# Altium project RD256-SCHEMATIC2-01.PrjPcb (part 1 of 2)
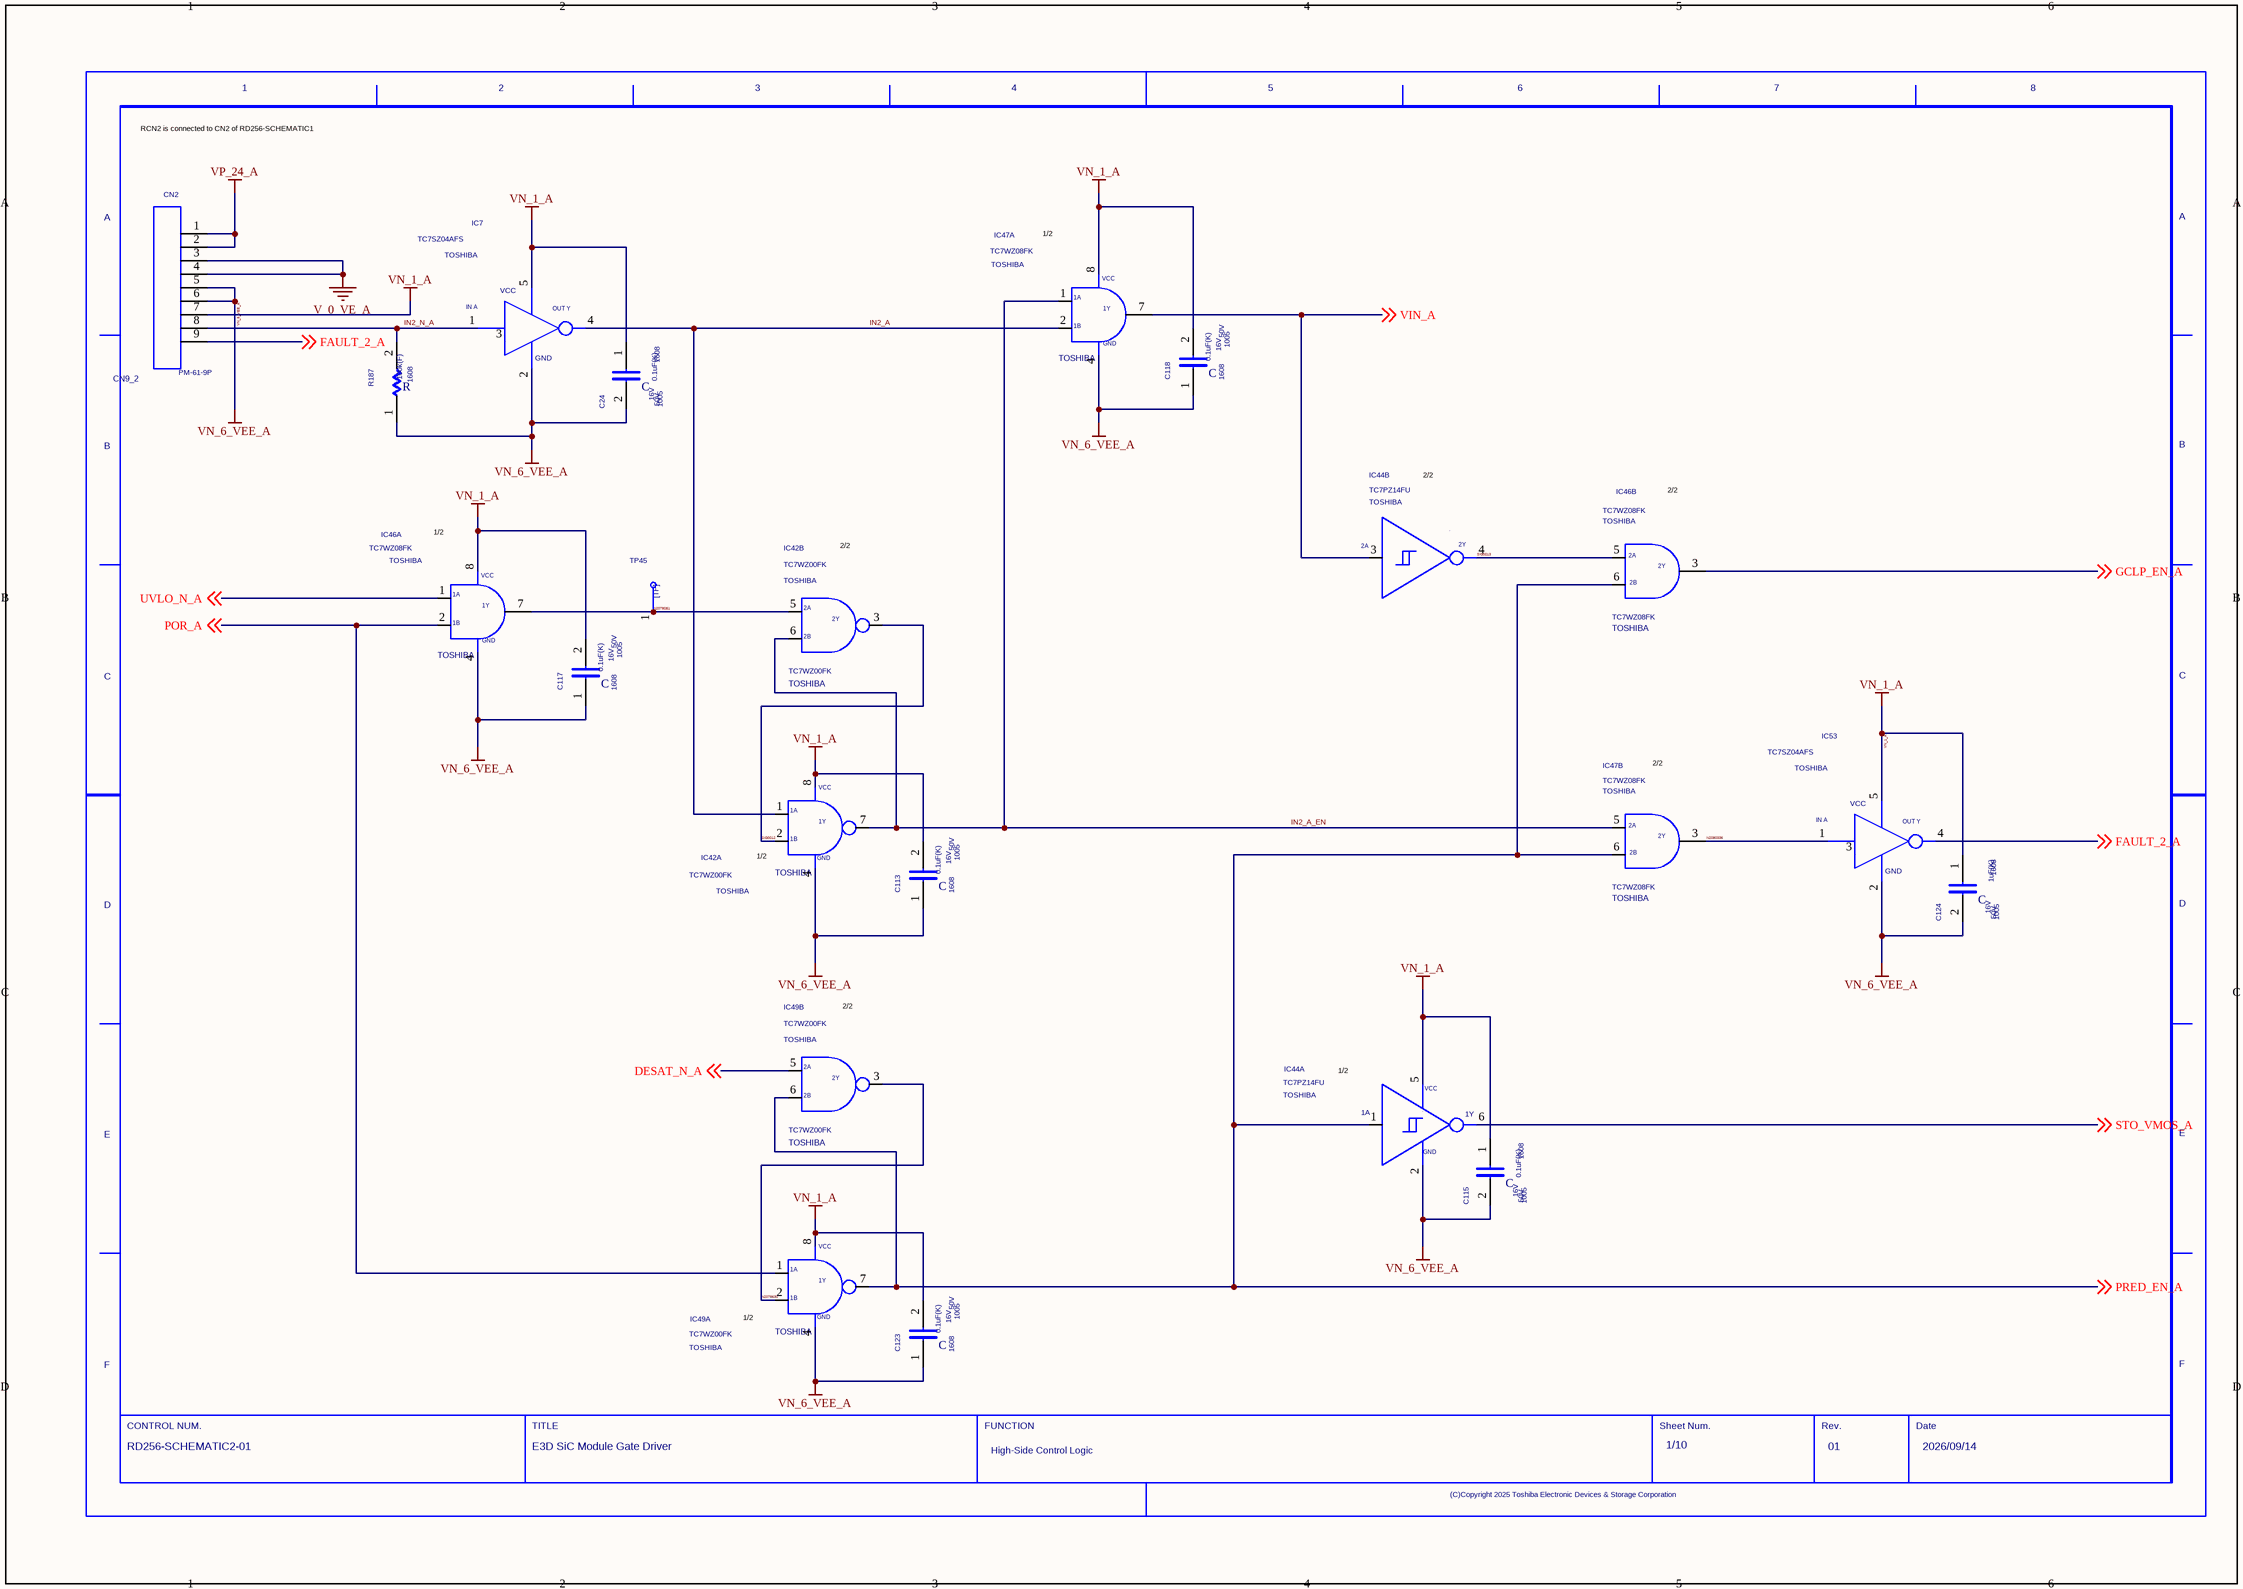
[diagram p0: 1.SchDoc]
10 sheets, 363 parts. Net scope: global (net labels, ports and power ports of the same name join across sheets).
Sheets:
  1.SchDoc
  2.SchDoc
  3.SchDoc
  4.SchDoc
  5.SchDoc
  6.SchDoc
  7.SchDoc
  8.SchDoc
  9.SchDoc
  10.SchDoc

## Sheet 1.SchDoc
size 420 x 297 mm

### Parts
(Parts that share a designator on the sheet are numbered #1, #2 ... from top to bottom, then left to right.)
C24  VOLTAGE: 16V  CODE: 1005  VAL1: 0.1uF(K)  VAL2: 50V  SIZECODESMD: 1608  (hidden comment: C)
C113  VOLTAGE: 16V  CODE: 1005  VAL1: 0.1uF(K)  VAL2: 50V  SIZECODESMD: 1608  (hidden comment: C)
C115  VOLTAGE: 16V  CODE: 1005  VAL1: 0.1uF(K)  VAL2: 50V  SIZECODESMD: 1608  (hidden comment: C)
C117  VOLTAGE: 16V  CODE: 1005  VAL1: 0.1uF(K)  VAL2: 50V  SIZECODESMD: 1608  (hidden comment: C)
C118  VOLTAGE: 16V  CODE: 1005  VAL1: 0.1uF(K)  VAL2: 50V  SIZECODESMD: 1608  (hidden comment: C)
C123  VOLTAGE: 16V  CODE: 1005  VAL1: 0.1uF(K)  VAL2: 50V  SIZECODESMD: 1608  (hidden comment: C)
C124  VOLTAGE: 16V  CODE: 1005  VAL1: 1uF(K)  VAL2: 50V  SIZECODESMD: 1608  (hidden comment: C)
CN2  CN9_2  VAL3: PM-61-9P
IC7  USERCOMPTEXT3: TOSHIBA  (hidden comment: TC7SZ04AFS)
IC42  VENDOR: TOSHIBA  (hidden comment: TC7WZ00FK)  (parts A,B of 2)
IC44  VAL3: TC7PZ14FU  USERCOMPTEXT3: TOSHIBA  (hidden comment: TC7PZ17FU)  (parts A,B of 2)
IC46  VENDOR: TOSHIBA  (hidden comment: TC7WZ08FK)  (parts A,B of 2)
IC47  VENDOR: TOSHIBA  (hidden comment: TC7WZ08FK)  (parts A,B of 2)
IC49  VENDOR: TOSHIBA  (hidden comment: TC7WZ00FK)  (parts A,B of 2)
IC53  USERCOMPTEXT3: TOSHIBA  (hidden comment: TC7SZ04AFS)
R187  VAL1: 100k(F)  SIZECODESMD: 1608  (hidden comment: R)
TP45  TP  (value not drawn)
U?#1  REVISION: 01  SHEETNUMBER: 1/10  FUNCTION: High-Side Control Logic  TITLE: E3D SiC Module Gate Driver  DRAWINGNUMBER: RD256-SCHEMATIC2-01  DATE: 2026/09/14  (hidden comment: WAKU_DEF100)

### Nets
V_0_VE_A: CN2.3 CN2.4
VN_1_A: C24.1 C113.2 C115.1 C117.2 C118.2 C123.2 C124.1 CN2.7 IC7.5 IC42.8 IC44.5 IC46.8 IC47.8 IC49.8 IC53.5
VN_6_VEE_A: C24.2 C113.1 C115.2 C117.1 C118.1 C123.1 C124.2 CN2.5 CN2.6 IC7.2 IC42.4 IC44.2 IC46.4 IC47.4 IC49.4 IC53.2 R187.1
VP_24_A: CN2.1 CN2.2
DESAT_N_A: IC49.5(2A) ; off-sheet DESAT_N_A
FAULT_2_A: CN2.9 IC53.4 ; off-sheet FAULT_2_A
GCLP_EN_A: IC46.3 ; off-sheet GCLP_EN_A
IN2_A: IC7.4 IC42.1 IC47.2
IN2_A_EN: IC42.6(2B) IC42.7 IC47.1 IC47.5
IN2_N_A: CN2.8 IC7.1 R187.2
N2078081: IC42.5(2A) IC46.7 TP45.1
N2078630: IC49.2 IC49.3(2Y)
N2080336: IC47.3 IC53.1
POR_A: IC46.2 IC49.1 ; off-sheet POR_A
PRED_EN_A: IC44.1 IC46.6 IC47.6 IC49.6(2B) IC49.7 ; off-sheet PRED_EN_A
SIG0012: IC42.2 IC42.3(2Y)
SIG0013: IC44.4 IC46.5
STO_VMOS_A: IC44.6 ; off-sheet STO_VMOS_A
UVLO_N_A: IC46.1 ; off-sheet UVLO_N_A
VIN_A: IC44.3 IC47.7 ; off-sheet VIN_A

Not connected (* = marked no-connect by the designer): IC7 3; IC53 3

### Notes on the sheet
- RCN2 is connected to CN2 of RD256-SCHEMATIC1
- (near IC47) 1/2
- (near IC46) 1/2
- 2/2
- (near IC42) 1/2
- (near IC44) 1/2
- (near IC49) 1/2

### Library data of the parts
C24 C113 C115 C117 C118 C123 C124 = C: ORIGINALSYMBOLORIGIN: (0,0); VC2: 0; PSPICETEMPLATE: C^@REFDES %1 %2 ?TOLERANCE¦C^@REFDES¦ @VALUE ?IC/IC=@IC/ TC=@TC1,@TC2 ?TOLERANCE¦\n.model C^@REFDES CAP C=1 DEV=@TOLERANCE% TC1=@TC1 TC2=@TC2 VC1=@VC1 VC2=@VC2¦; SAVECOUNT: 2; UPDATETIME: 08:48:12; UPDATEUSER: HP_Z8_KEYSHOT; INSTANCENAME: INS2265204
CN2 = CN9_1: OriginalSymbolOrigin: (0,0); USER_VALUE: XG4A-1031; PSPICETEMPLATE: X^@REFDES %1 %2 %3 %4 %5 %6 %7 %8 %9 %10 %M1 %M2 @MODEL; SAVECOUNT: 2; UPDATETIME: 08:48:13; UPDATEUSER: HP_Z8_KEYSHOT; INSTANCENAME: INS2253568
IC7 IC53 = TC7SZ04AFS: OriginalSymbolOrigin: (0,-5080); PSPICETEMPLATE: X^@REFDES %INA %GND %NC %OUTY %VCC @MODEL; SAVECOUNT: 6; UPDATETIME: 19:30:29; UPDATEUSER: t5459927; TIME: 11:55:02; INSTANCENAME: INS2254048
IC42 IC49 = TC7WZ00FK_2: PART NUMBER: TC7W00FK; ORIGINALSYMBOLORIGIN: (2540,-2540); DESCRIPTION-A: NAND 2ch Logic; PSPICETEMPLATE: X^@REFDES %1A %1B %2Y %GND %2A %2B %1Y %VCC @MODEL; ・: 7 V; SPLIT_INST: TRUE; ORDER: $pOrder; SWAP_INFO: (S1+S2); SAVECOUNT: 5; UPDATETIME: 16:09:46; UPDATEUSER: sptcae09; TIME: 08:52:39; INSTANCENAME: INS2253652; FUNCN: TC7WZ00FK_1; CaptureCellPackProp: TC7WZ00FK_2A
IC44 = TC7PZ14FU_2: OriginalSymbolOrigin: (5080,15240); SWAP_INFO: (S1+S2); PSPICETEMPLATE: X^@REFDES %1A %GND %2A %2Y %VCC %1Y @MODEL; SPLIT_INST: TRUE; SAVECOUNT: 7; UPDATETIME: 19:09:34; UPDATEUSER: t5459927; TIME: 11:55:01; INSTANCENAME: INS2254016; FUNCN: TC7PZ14FU_1; CaptureCellPackProp: TC7PZ14FU_2A
IC46 IC47 = TC7WZ08FK_1: PART NUMBER: TC7W00FK; ORIGINALSYMBOLORIGIN: (2540,-2540); DESCRIPTION-A: NAND 2ch Logic; PSPICETEMPLATE: X^@REFDES %1A %1B %2Y %GND %2A %2B %1Y %VCC @MODEL; ・: 7 V; SPLIT_INST: TRUE; ORDER: $pOrder; SWAP_INFO: (S1+S2); SAVECOUNT: 5; UPDATETIME: 16:09:46; UPDATEUSER: sptcae09; TIME: 08:52:39; INSTANCENAME: INS2254084; CaptureCellPackProp: TC7WZ08FK_1A
R187 = R: ORIGINALSYMBOLORIGIN: (0,0); PSPICETEMPLATE: R^@REFDES %1 %2 ?TOLERANCE¦R^@REFDES¦ @VALUE TC=@TC1,@TC2 ?TOLERANCE¦\n.model R^@REFDES RES R=1 DEV=@TOLERANCE% TC1=@TC1 TC2=@TC2¦; TC2: 0; VAL2: 100mW; SAVECOUNT: 2; UPDATETIME: 08:48:13; UPDATEUSER: HP_Z8_KEYSHOT; INSTANCENAME: INS2263832
TP45 = TP: ORIGINALSYMBOLORIGIN: (0,0); SAVEAREA0: -242,-92,12810,7836; SAVECOUNT: 2; UPDATETIME: 16:18:11; UPDATEUSER: fukuda-y; TIME: 16:12:21; INSTANCENAME: INS2253720
U?#1 = WAKU_DEF100: OriginalSymbolOrigin: (10160,284480); SAVECOUNT: 4; UPDATETIME: 12:22:00; UPDATEUSER: t5459927; TIME: 14:30:25; SAVEAREA0: -63393,-16950,474261,314592; PLOTTIME: HH:MM; SHTSAVECOUNT: 35

## Sheet 2.SchDoc
size 420 x 297 mm
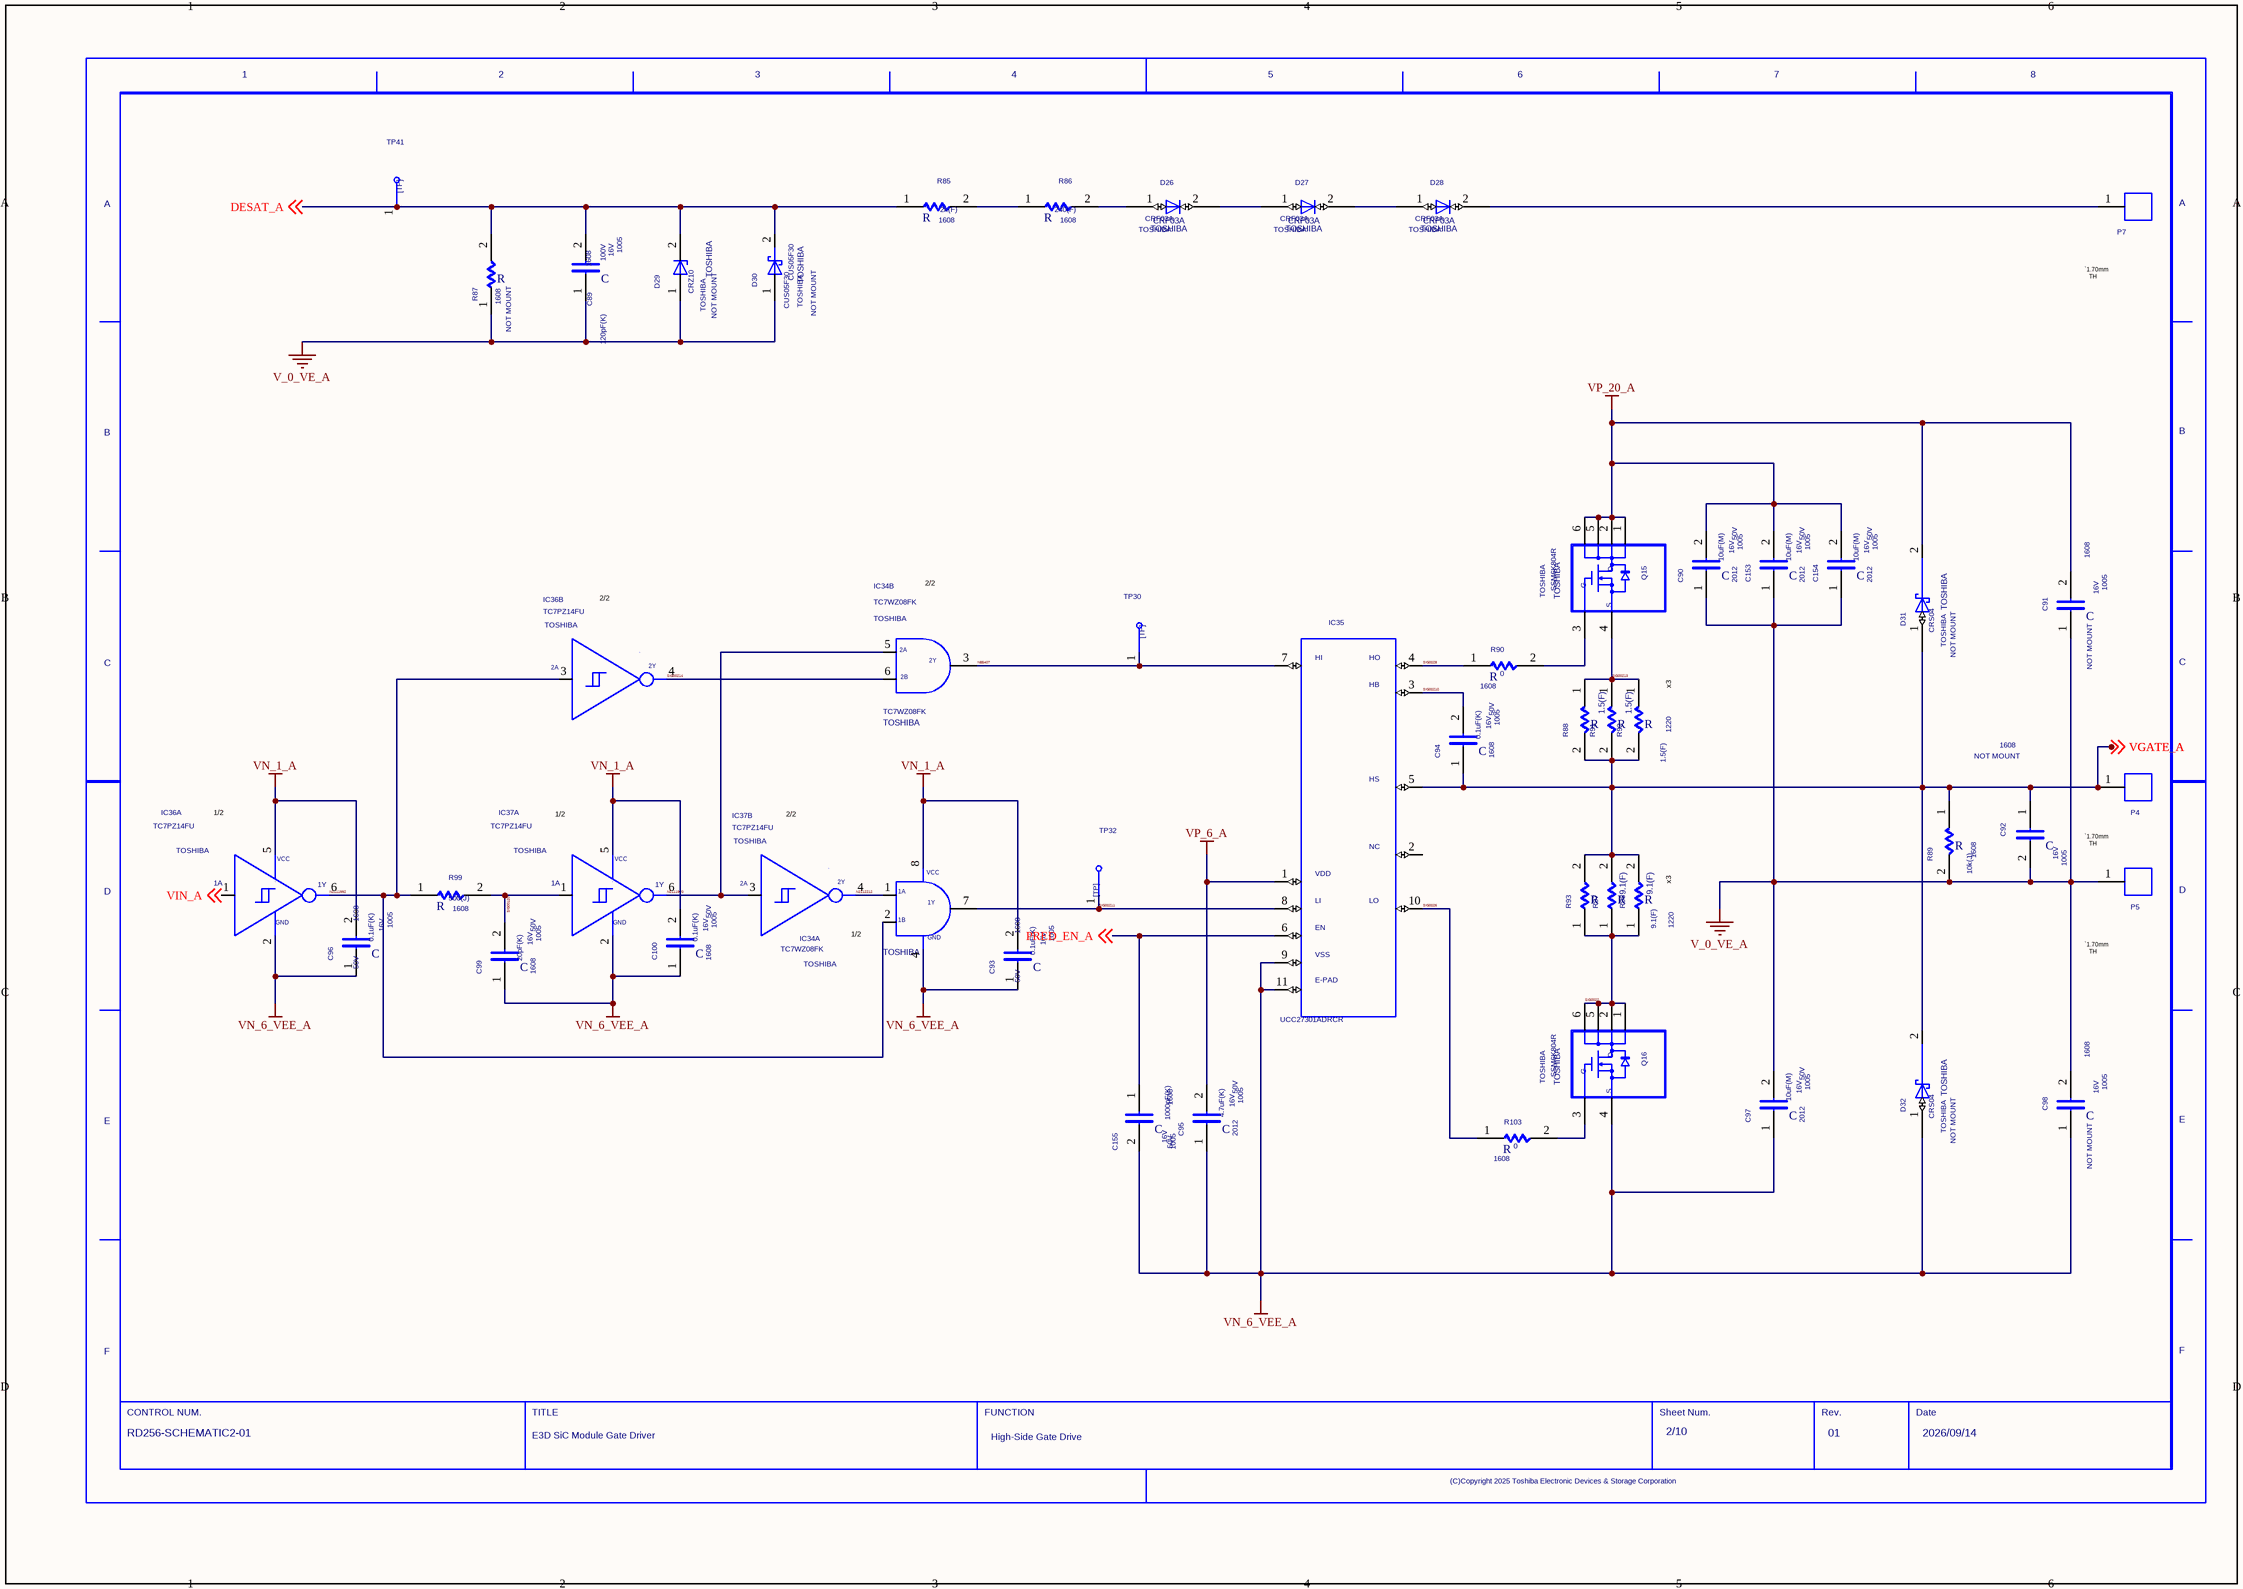
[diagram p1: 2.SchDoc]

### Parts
(Parts that share a designator on the sheet are numbered #1, #2 ... from top to bottom, then left to right.)
C89  VOLTAGE: 16V  CODE: 1005  VAL1: 120pF(K)  VAL2: 100V  SIZECODESMD: 1608  (hidden comment: C)
C90  VOLTAGE: 16V  CODE: 1005  VAL1: 10uF(M)  VAL2: 50V  SIZECODESMD: 2012  (hidden comment: C)
C91  VOLTAGE: 16V  CODE: 1005  SIZECODESMD: 1608  NOTMOUNT: NOT MOUNT  (hidden comment: C)
C92  VOLTAGE: 16V  CODE: 1005  SIZECODESMD: 1608  NOTMOUNT: NOT MOUNT  (hidden comment: C)
C93  VOLTAGE: 16V  CODE: 1005  VAL1: 0.1uF(K)  VAL2: 50V  SIZECODESMD: 1608  (hidden comment: C)
C94  VOLTAGE: 16V  CODE: 1005  VAL1: 0.1uF(K)  VAL2: 50V  SIZECODESMD: 1608  (hidden comment: C)
C95  VOLTAGE: 16V  CODE: 1005  VAL1: 4.7uF(K)  VAL2: 50V  SIZECODESMD: 2012  (hidden comment: C)
C96  VOLTAGE: 16V  CODE: 1005  VAL1: 0.1uF(K)  VAL2: 50V  SIZECODESMD: 1608  (hidden comment: C)
C97  VOLTAGE: 16V  CODE: 1005  VAL1: 10uF(M)  VAL2: 50V  SIZECODESMD: 2012  (hidden comment: C)
C98  VOLTAGE: 16V  CODE: 1005  SIZECODESMD: 1608  NOTMOUNT: NOT MOUNT  (hidden comment: C)
C99  VOLTAGE: 16V  CODE: 1005  VAL1: 20pF(K)  VAL2: 50V  SIZECODESMD: 1608  (hidden comment: C)
C100  VOLTAGE: 16V  CODE: 1005  VAL1: 0.1uF(K)  VAL2: 50V  SIZECODESMD: 1608  (hidden comment: C)
C153  VOLTAGE: 16V  CODE: 1005  VAL1: 10uF(M)  VAL2: 50V  SIZECODESMD: 2012  (hidden comment: C)
C154  VOLTAGE: 16V  CODE: 1005  VAL1: 10uF(M)  VAL2: 50V  SIZECODESMD: 2012  (hidden comment: C)
C155  VOLTAGE: 16V  CODE: 1005  VAL1: 1000pF(K)  VAL2: 50V  SIZECODESMD: 1608  (hidden comment: C)
D26  VENDOR: TOSHIBA  (hidden comment: CRF03A)
D27  VENDOR: TOSHIBA  (hidden comment: CRF03A)
D28  VENDOR: TOSHIBA  (hidden comment: CRF03A)
D29  VENDOR: TOSHIBA  NOTMOUNT: NOT MOUNT  (hidden comment: CRZ10)
D30  VENDOR: TOSHIBA  NOTMOUNT: NOT MOUNT  (hidden comment: CUS05F30)
D31  VENDOR: TOSHIBA  NOTMOUNT: NOT MOUNT  (hidden comment: CRS04)
D32  VENDOR: TOSHIBA  NOTMOUNT: NOT MOUNT  (hidden comment: CRS04)
IC34  VENDOR: TOSHIBA  (hidden comment: TC7WZ08FK)  (parts A,B of 2)
IC35  VAL3: UCC27301ADRCR  (hidden comment: UCC27301A)
IC36  VAL3: TC7PZ14FU  USERCOMPTEXT3: TOSHIBA  (hidden comment: TC7PZ17FU)  (parts A,B of 2)
IC37  VAL3: TC7PZ14FU  USERCOMPTEXT3: TOSHIBA  (hidden comment: TC7PZ17FU)  (parts A,B of 2)
P4  TH  (value not drawn)
P5  TH  (value not drawn)
P7  TH  (value not drawn)
Q15  VENDOR: TOSHIBA  (hidden comment: SSM6K804R)
Q16  VENDOR: TOSHIBA  (hidden comment: SSM6K804R)
R85  VAL1: 2k(F)  SIZECODESMD: 1608  (hidden comment: R)
R86  VAL1: 240(F)  SIZECODESMD: 1608  (hidden comment: R)
R87  SIZECODESMD: 1608  NOTMOUNT: NOT MOUNT  (hidden comment: R)
R88  VAL1: 1.5(F)  SIZECODESMD: 1220  (hidden comment: R)
R89  VAL1: 10k(J)  SIZECODESMD: 1608  (hidden comment: R)
R90  VAL1: 0  SIZECODESMD: 1608  (hidden comment: R)
R91  VAL1: 1.5(F)  (hidden comment: R)
R92  VAL1: 1.5(F)  (hidden comment: R)
R93  VAL1: 9.1(F)  SIZECODESMD: 1220  (hidden comment: R)
R97  VAL1: 9.1(F)  (hidden comment: R)
R98  VAL1: 9.1(F)  (hidden comment: R)
R99  VAL1: 500(J)  SIZECODESMD: 1608  (hidden comment: R)
R103  VAL1: 0  SIZECODESMD: 1608  (hidden comment: R)
TP30  TP  (value not drawn)
TP32  TP  (value not drawn)
TP41  TP  (value not drawn)
U?#2  REVISION: 01  SHEETNUMBER: 2/10  FUNCTION: High-Side Gate Drive  TITLE: E3D SiC Module Gate Driver  DRAWINGNUMBER: RD256-SCHEMATIC2-01  DATE: 2026/09/14  (hidden comment: WAKU_DEF100)

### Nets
V_0_VE_A: C89.1 C90.1 C91.1 C92.2 C97.2 C98.2 C153.1 C154.1 D29.1(A) D30.1(A) P5.1 R87.1 R89.2
VN_1_A: C93.2 C96.2 C100.2 IC34.8 IC36.5 IC37.5
VN_6_VEE_A: C93.1 C95.1 C96.1 C97.1 C98.1 C99.1 C100.1 C155.2 D32.1(A) IC34.4 IC35.9 IC35.11 IC36.2 IC37.2 Q16.4
VP_6_A: C95.2 IC35.1
VP_20_A: C90.2 C91.2 C153.2 C154.2 D31.2(C) Q15.1 Q15.2 Q15.5 Q15.6
DESAT_A: C89.2 D29.2(C) D30.2(C) R85.1 R87.2 TP41.1 ; off-sheet DESAT_A
N85407: IC34.3 IC35.7 TP30.1
N2111970: IC34.5 IC37.3 IC37.6
N2111992: IC34.2 IC36.3 IC36.6 R99.1
N2112212: IC34.1 IC37.4
PRED_EN_A: C155.1 IC35.6 ; off-sheet PRED_EN_A
SIG0022: Q16.1 Q16.2 Q16.5 Q16.6 R93.1 R97.1 R98.1
SIG0026: IC35.10 R103.1
SIG0028: IC35.4 R90.1
SIG00120: C99.2 IC37.1 R99.2
SIG00130: Q16.3 R103.2
SIG00136: Q15.3 R90.2
SIG00137: R85.2 R86.1
SIG00138: D26.1(A) R86.2
SIG00139: D26.2(C) D27.1(A)
SIG00140: D27.2(C) D28.1(A)
SIG00141: D28.2(C) P7.1
SIG00210: C94.2 IC35.3
SIG00211: IC34.7 IC35.8 TP32.1
SIG00213: Q15.4 R88.1 R91.1 R92.1
SIG00214: IC34.6 IC36.4
VGATE_A: C92.1 C94.1 D31.1(A) D32.2(C) IC35.5 P4.1 R88.2 R89.1 R91.2 R92.2 R93.2 R97.2 R98.2 ; off-sheet VGATE_A
VIN_A: IC36.1 ; off-sheet VIN_A

Not connected (* = marked no-connect by the designer): IC35 2

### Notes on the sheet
- `1.70mm
  TH
- 2/2
- (near R92) x3
- (near IC36) 1/2
- (near IC37) 1/2
- 1/2
- (near R98) x3

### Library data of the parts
C89 C90 C93-C97 C99 C100 C153-C155 = C: as C24 on sheet 1
C91 C92 C98 = C: ORIGINALSYMBOLORIGIN: (0,0); VC2: 0; PSPICETEMPLATE: C^@REFDES %1 %2 ?TOLERANCE¦C^@REFDES¦ @VALUE ?IC/IC=@IC/ TC=@TC1,@TC2 ?TOLERANCE¦\n.model C^@REFDES CAP C=1 DEV=@TOLERANCE% TC1=@TC1 TC2=@TC2 VC1=@VC1 VC2=@VC2¦; SAVECOUNT: 2; UPDATETIME: 08:48:12; UPDATEUSER: HP_Z8_KEYSHOT; INSTANCENAME: INS2266227
D26-D28 = CRF03A: OriginalSymbolOrigin: (0,0); PSPICETEMPLATE: X^@REFDES %A %C @MODEL; SAVECOUNT: 2; UPDATETIME: 08:48:14; UPDATEUSER: HP_Z8_KEYSHOT; INSTANCENAME: INS2254974
D29 = CRZ10: ORIGINALSYMBOLORIGIN: (0,0); PSPICETEMPLATE: X^@REFDES %A %C @MODEL; SAVEAREA0: -4630,-153,17114,13055; SAVECOUNT: 6; UPDATETIME: 08:18:42; UPDATEUSER: fukuda-y; TIME: 14:49:55; INSTANCENAME: INS2255026
D30 = CUS05F30: ORIGINALSYMBOLORIGIN: (0,0); PSPICETEMPLATE: X^@REFDES %A %C @MODEL; SAVEAREA0: -4630,-153,17114,13055; SAVECOUNT: 9; UPDATETIME: 08:16:22; UPDATEUSER: fukuda-y; TIME: 14:49:55; INSTANCENAME: INS2255944
D31 D32 = CRS04: OriginalSymbolOrigin: (0,0); PSPICETEMPLATE: X^@REFDES %A %C @MODEL; SAVECOUNT: 2; UPDATETIME: 08:48:14; UPDATEUSER: HP_Z8_KEYSHOT; INSTANCENAME: INS2256112
IC34 = TC7WZ08FK_1: PART NUMBER: TC7W00FK; ORIGINALSYMBOLORIGIN: (2540,-2540); DESCRIPTION-A: NAND 2ch Logic; PSPICETEMPLATE: X^@REFDES %1A %1B %2Y %GND %2A %2B %1Y %VCC @MODEL; ・: 7 V; SPLIT_INST: TRUE; ORDER: $pOrder; SWAP_INFO: (S1+S2); SAVECOUNT: 9; UPDATETIME: 16:09:46; UPDATEUSER: sptcae09; TIME: 08:52:39; INSTANCENAME: INS2255192; CaptureCellPackProp: TC7WZ08FK_1A
IC35 = UCC27301A: OriginalSymbolOrigin: (5080,60960); PSPICETEMPLATE: X^@REFDES %VDD %NC %HB %HO %HS %EN %HI %LI %VSS %LO %THERMAL_PAD @MODEL; SAVECOUNT: 11; UPDATETIME: 20:55:41; UPDATEUSER: t5459927; TIME: 08:48:14
IC36 IC37 = TC7PZ14FU_2: OriginalSymbolOrigin: (5080,15240); SWAP_INFO: (S1+S2); PSPICETEMPLATE: X^@REFDES %1A %GND %2A %2Y %VCC %1Y @MODEL; SPLIT_INST: TRUE; SAVECOUNT: 7; UPDATETIME: 19:09:34; UPDATEUSER: t5459927; TIME: 11:55:01; INSTANCENAME: INS2255542; FUNCN: TC7PZ14FU_1; CaptureCellPackProp: TC7PZ14FU_2A
P4 = TH: ORIGINALSYMBOLORIGIN: (0,0); PSPICETEMPLATE: X^@REFDES %1 @MODEL; SAVECOUNT: 1; UPDATETIME: 18:11:32; UPDATEUSER: w20165dm; INSTANCENAME: INS2255180
P5 = TH: ORIGINALSYMBOLORIGIN: (0,0); PSPICETEMPLATE: X^@REFDES %1 @MODEL; SAVECOUNT: 1; UPDATETIME: 18:11:32; UPDATEUSER: w20165dm; INSTANCENAME: INS2256066
P7 = TH: ORIGINALSYMBOLORIGIN: (0,0); PSPICETEMPLATE: X^@REFDES %1 @MODEL; SAVECOUNT: 1; UPDATETIME: 18:11:32; UPDATEUSER: w20165dm; INSTANCENAME: INS2255754
Q15 Q16 = SSM6K804R: PSPICETEMPLATE: X^@REFDES %1 %2 %3 %4 %5 %6 @MODEL; ORIGINALSYMBOLORIGIN: (0,0); SAVEAREA0: -7120,-295,29516,23636; SAVECOUNT: 14; UPDATETIME: 08:48:15; UPDATEUSER: HP_Z8_KEYSHOT; INSTANCENAME: INS2255292
R85 R86 R99 = R: as R187 on sheet 1
R87 = R: ORIGINALSYMBOLORIGIN: (0,0); PSPICETEMPLATE: R^@REFDES %1 %2 ?TOLERANCE¦R^@REFDES¦ @VALUE TC=@TC1,@TC2 ?TOLERANCE¦\n.model R^@REFDES RES R=1 DEV=@TOLERANCE% TC1=@TC1 TC2=@TC2¦; TC2: 0; VAL2: 0.125; SAVECOUNT: 2; UPDATETIME: 08:48:13; UPDATEUSER: HP_Z8_KEYSHOT; INSTANCENAME: INS2263832
R88 R93 = R: ORIGINALSYMBOLORIGIN: (0,0); PSPICETEMPLATE: R^@REFDES %1 %2 ?TOLERANCE¦R^@REFDES¦ @VALUE TC=@TC1,@TC2 ?TOLERANCE¦\n.model R^@REFDES RES R=1 DEV=@TOLERANCE% TC1=@TC1 TC2=@TC2¦; TC2: 0; VAL2: 1W; SAVECOUNT: 2; UPDATETIME: 08:48:13; UPDATEUSER: HP_Z8_KEYSHOT; INSTANCENAME: INS2256002
R89 = R: ORIGINALSYMBOLORIGIN: (0,0); PSPICETEMPLATE: R^@REFDES %1 %2 ?TOLERANCE¦R^@REFDES¦ @VALUE TC=@TC1,@TC2 ?TOLERANCE¦\n.model R^@REFDES RES R=1 DEV=@TOLERANCE% TC1=@TC1 TC2=@TC2¦; TC2: 0; VAL2: 100mW; SAVECOUNT: 2; UPDATETIME: 08:48:13; UPDATEUSER: HP_Z8_KEYSHOT; INSTANCENAME: INS2266059
R90 R103 = R: ORIGINALSYMBOLORIGIN: (0,0); PSPICETEMPLATE: R^@REFDES %1 %2 ?TOLERANCE¦R^@REFDES¦ @VALUE TC=@TC1,@TC2 ?TOLERANCE¦\n.model R^@REFDES RES R=1 DEV=@TOLERANCE% TC1=@TC1 TC2=@TC2¦; VAL2: 0.125; SAVECOUNT: 2; UPDATETIME: 08:48:13; UPDATEUSER: HP_Z8_KEYSHOT; INSTANCENAME: INS2256002
R91 R92 R97 R98 = R: ORIGINALSYMBOLORIGIN: (0,0); PSPICETEMPLATE: R^@REFDES %1 %2 ?TOLERANCE¦R^@REFDES¦ @VALUE TC=@TC1,@TC2 ?TOLERANCE¦\n.model R^@REFDES RES R=1 DEV=@TOLERANCE% TC1=@TC1 TC2=@TC2¦; TC2: 0; VAL2: 1W; SAVECOUNT: 2; UPDATETIME: 08:48:13; UPDATEUSER: HP_Z8_KEYSHOT; INSTANCENAME: INS2256002; SIZECODESMD: 1220
TP30 = TP: ORIGINALSYMBOLORIGIN: (0,0); SAVEAREA0: -242,-92,12810,7836; SAVECOUNT: 2; UPDATETIME: 16:18:11; UPDATEUSER: fukuda-y; TIME: 16:12:21; INSTANCENAME: INS2255892
TP32 = TP: ORIGINALSYMBOLORIGIN: (0,0); SAVEAREA0: -242,-92,12810,7836; SAVECOUNT: 2; UPDATETIME: 16:18:11; UPDATEUSER: fukuda-y; TIME: 16:12:21; INSTANCENAME: INS2255530
TP41 = TP: ORIGINALSYMBOLORIGIN: (0,0); SAVEAREA0: -242,-92,12810,7836; SAVECOUNT: 2; UPDATETIME: 16:18:11; UPDATEUSER: fukuda-y; TIME: 16:12:21; INSTANCENAME: INS2255794
U?#2 = WAKU_DEF100: OriginalSymbolOrigin: (10160,284480); SAVECOUNT: 4; UPDATETIME: 12:22:00; UPDATEUSER: t5459927; TIME: 14:30:25; SAVEAREA0: -63393,-16950,474261,314592; PLOTTIME: HH:MM; SHTSAVECOUNT: 39

## Sheet 3.SchDoc
size 420 x 297 mm
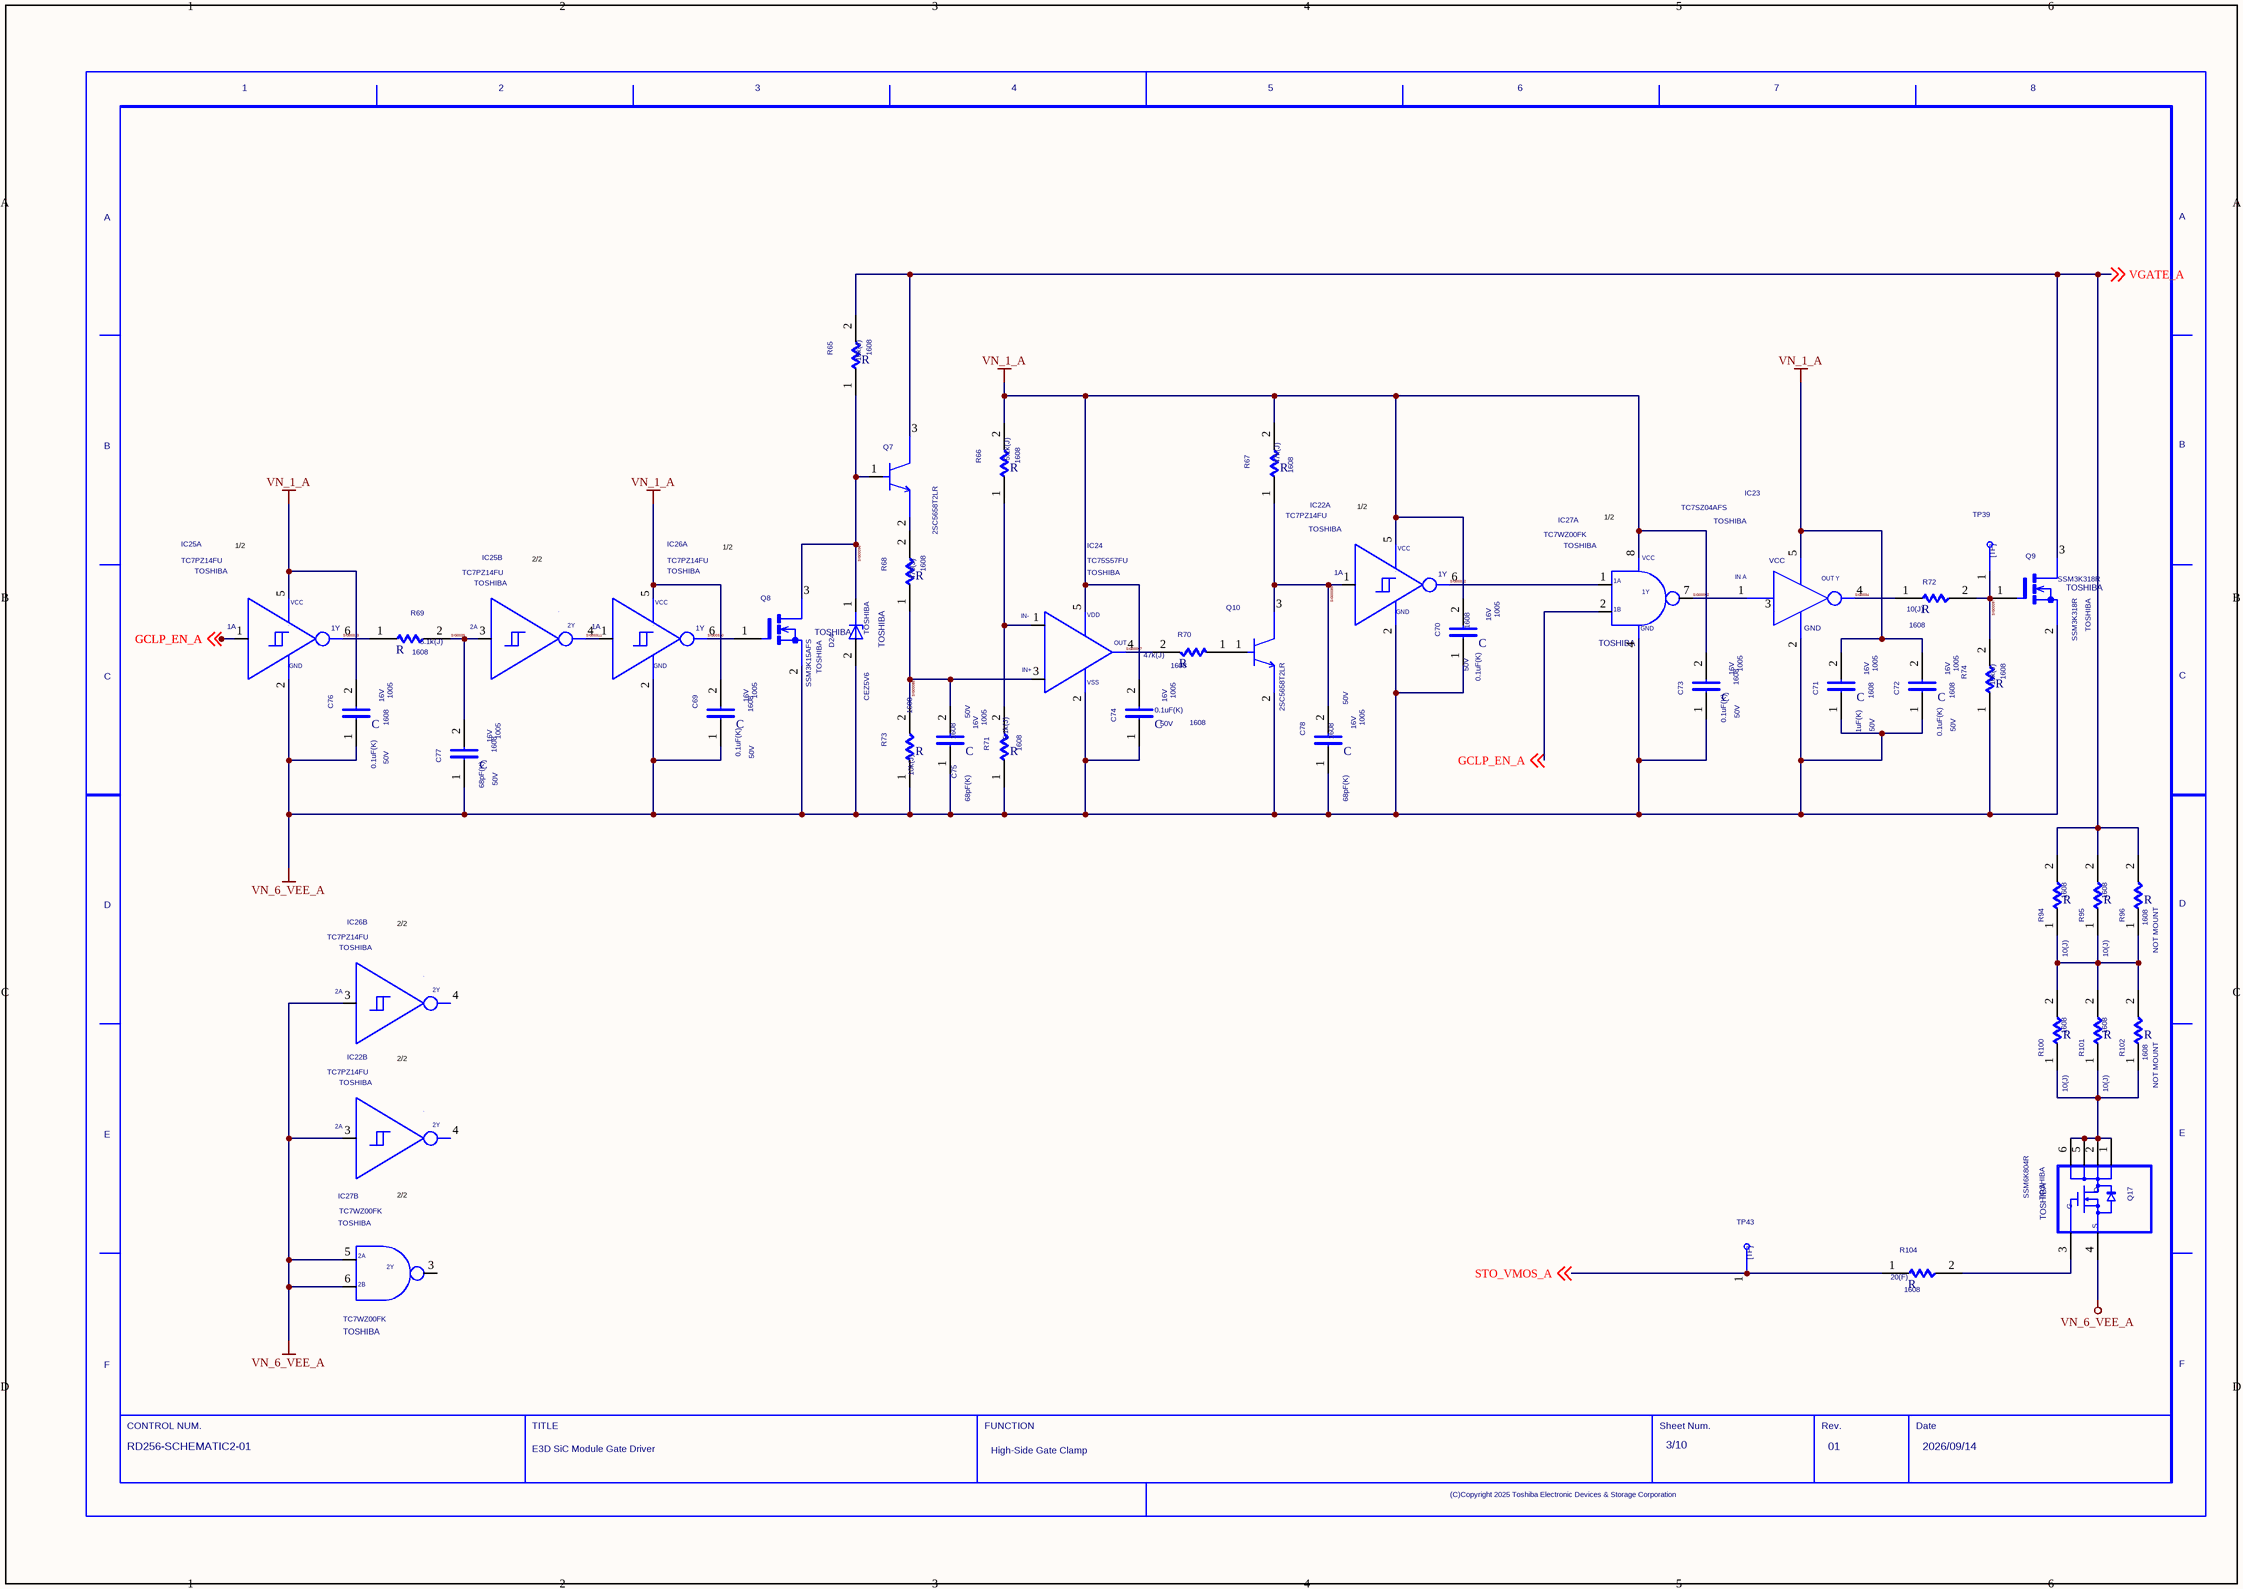
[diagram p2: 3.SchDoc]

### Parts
(Parts that share a designator on the sheet are numbered #1, #2 ... from top to bottom, then left to right.)
C69  VOLTAGE: 16V  CODE: 1005  VAL1: 0.1uF(K)  VAL2: 50V  SIZECODESMD: 1608  (hidden comment: C)
C70  VOLTAGE: 16V  CODE: 1005  VAL1: 0.1uF(K)  VAL2: 50V  SIZECODESMD: 1608  (hidden comment: C)
C71  VOLTAGE: 16V  CODE: 1005  VAL1: 1uF(K)  VAL2: 50V  SIZECODESMD: 1608  (hidden comment: C)
C72  VOLTAGE: 16V  CODE: 1005  VAL1: 0.1uF(K)  VAL2: 50V  SIZECODESMD: 1608  (hidden comment: C)
C73  VOLTAGE: 16V  CODE: 1005  VAL1: 0.1uF(K)  VAL2: 50V  SIZECODESMD: 1608  (hidden comment: C)
C74  VOLTAGE: 16V  CODE: 1005  VAL1: 0.1uF(K)  VAL2: 50V  SIZECODESMD: 1608  (hidden comment: C)
C75  VOLTAGE: 16V  CODE: 1005  VAL1: 68pF(K)  VAL2: 50V  SIZECODESMD: 1608  (hidden comment: C)
C76  VOLTAGE: 16V  CODE: 1005  VAL1: 0.1uF(K)  VAL2: 50V  SIZECODESMD: 1608  (hidden comment: C)
C77  VOLTAGE: 16V  CODE: 1005  VAL1: 68pF(K)  VAL2: 50V  SIZECODESMD: 1608  (hidden comment: C)
C78  VOLTAGE: 16V  CODE: 1005  VAL1: 68pF(K)  VAL2: 50V  SIZECODESMD: 1608  (hidden comment: C)
D24  VENDOR: TOSHIBA  (hidden comment: CEZ5V6)
IC22  VAL3: TC7PZ14FU  USERCOMPTEXT3: TOSHIBA  (hidden comment: TC7PZ17FU)  (parts A,B of 2)
IC23  USERCOMPTEXT3: TOSHIBA  (hidden comment: TC7SZ04AFS)
IC24  USERCOMPTEXT3: TOSHIBA  (hidden comment: TC75S57FU)
IC25  VAL3: TC7PZ14FU  USERCOMPTEXT3: TOSHIBA  (hidden comment: TC7PZ17FU)  (parts A,B of 2)
IC26  VAL3: TC7PZ14FU  USERCOMPTEXT3: TOSHIBA  (hidden comment: TC7PZ17FU)  (parts A,B of 2)
IC27  VENDOR: TOSHIBA  (hidden comment: TC7WZ00FK)  (parts A,B of 2)
Q7  VAL3: 2SC5658T2LR  (hidden comment: 2SC5658J)
Q8  VENDOR: TOSHIBA  (hidden comment: SSM3K15AFS)
Q9  VENDOR: TOSHIBA  (hidden comment: SSM3K318R)
Q10  VAL3: 2SC5658T2LR  (hidden comment: 2SC5658J)
Q17  VENDOR: TOSHIBA  (hidden comment: SSM6K804R)
R65  VAL1: 10k(J)  SIZECODESMD: 1608  (hidden comment: R)
R66  VAL1: 5.1k(J)  SIZECODESMD: 1608  (hidden comment: R)
R67  VAL1: 47k(J)  SIZECODESMD: 1608  (hidden comment: R)
R68  VAL1: 470(J)  SIZECODESMD: 1608  (hidden comment: R)
R69  VAL1: 5.1k(J)  SIZECODESMD: 1608  (hidden comment: R)
R70  VAL1: 47k(J)  SIZECODESMD: 1608  (hidden comment: R)
R71  VAL1: 5.1k(J)  SIZECODESMD: 1608  (hidden comment: R)
R72  VAL1: 10(J)  SIZECODESMD: 1608  (hidden comment: R)
R73  VAL1: 10k(J)  SIZECODESMD: 1608  (hidden comment: R)
R74  VAL1: 10k(J)  SIZECODESMD: 1608  (hidden comment: R)
R94  VAL1: 10(J)  SIZECODESMD: 1608  (hidden comment: R)
R95  VAL1: 10(J)  SIZECODESMD: 1608  (hidden comment: R)
R96  SIZECODESMD: 1608  NOTMOUNT: NOT MOUNT  (hidden comment: R)
R100  VAL1: 10(J)  SIZECODESMD: 1608  (hidden comment: R)
R101  VAL1: 10(J)  SIZECODESMD: 1608  (hidden comment: R)
R102  SIZECODESMD: 1608  NOTMOUNT: NOT MOUNT  (hidden comment: R)
R104  VAL1: 20(F)  SIZECODESMD: 1608  (hidden comment: R)
TP39  TP  (value not drawn)
TP43  TP  (value not drawn)
U?#3  REVISION: 01  SHEETNUMBER: 3/10  FUNCTION: High-Side Gate Clamp  TITLE: E3D SiC Module Gate Driver  DRAWINGNUMBER: RD256-SCHEMATIC2-01  DATE: 2026/09/14  (hidden comment: WAKU_DEF100)

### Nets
VN_1_A: C69.2 C70.2 C71.2 C72.2 C73.2 C74.2 C76.2 IC22.5 IC23.5 IC24.5 IC25.5 IC26.5 IC27.8 R66.2 R67.2
VN_6_VEE_A: C69.1 C70.1 C71.1 C72.1 C73.1 C74.1 C75.1 C76.1 C77.1 C78.1 D24.2(A) IC22.2 IC22.3 IC23.2 IC24.2 IC25.2 IC26.2 IC26.3 IC27.4 IC27.5(2A) IC27.6(2B) Q8.2(S) Q9.2(S) Q10.2(E) Q17.4 R71.1 R73.1 R74.1
GCLP_EN_A: IC25.1 IC27.2 ; off-sheet GCLP_EN_A
SIG0034: IC23.4 R72.1
SIG0039: C77.2 IC25.3 R69.2
SIG00085: C75.2 IC24.3 R68.1 R73.2
SIG00086: IC24.1 R66.1 R71.2
SIG00087: IC24.4 R70.2
SIG00089: C78.2 IC22.1 Q10.3(C) R67.1
SIG00092: IC23.1 IC27.7
SIG00096: D24.1(C) Q7.1(B) Q8.3(D) R65.1
SIG00097: Q9.1(G) R72.2 R74.2 TP39.1
SIG00098: Q7.2(E) R68.2
SIG00133: Q17.1 Q17.2 Q17.5 Q17.6 R100.1 R101.1 R102.1
SIG00134: Q17.3 R104.2
SIG00135: R94.1 R95.1 R96.1 R100.2 R101.2 R102.2
SIG00310: IC26.6 Q8.1(G)
SIG00311: IC25.4 IC26.1
SIG00312: IC22.6 IC27.1
SIG00313: IC25.6 R69.1
STO_VMOS_A: R104.1 TP43.1 ; off-sheet STO_VMOS_A
VGATE_A: Q7.3(C) Q9.3(D) R65.2 R94.2 R95.2 R96.2 ; off-sheet VGATE_A
NetQ10_1: Q10.1(B) R70.1

Not connected (* = marked no-connect by the designer): IC22 4; IC23 3; IC26 4; IC27 3(2Y)

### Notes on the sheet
- (near IC22) 1/2
- (near IC27) 1/2
- (near IC25) 1/2
- 2/2
- 1/2

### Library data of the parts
C69-C78 = C: as C24 on sheet 1
D24 = CEZ5V6: ORIGINALSYMBOLORIGIN: (0,0); PSPICETEMPLATE: X^@REFDES %C %A @MODEL; SAVEAREA0: -4630,-153,17114,13055; SAVECOUNT: 9; UPDATETIME: 08:16:22; UPDATEUSER: fukuda-y; TIME: 14:49:55; INSTANCENAME: INS2262356
IC22 IC25 IC26 = TC7PZ14FU_2: OriginalSymbolOrigin: (5080,15240); SWAP_INFO: (S1+S2); PSPICETEMPLATE: X^@REFDES %1A %GND %2A %2Y %VCC %1Y @MODEL; SPLIT_INST: TRUE; SAVECOUNT: 7; UPDATETIME: 19:09:34; UPDATEUSER: t5459927; TIME: 11:55:01; FUNCN: TC7PZ14FU_1; CaptureCellPackProp: TC7PZ14FU_2A
IC23 = TC7SZ04AFS: OriginalSymbolOrigin: (0,-5080); PSPICETEMPLATE: X^@REFDES %INA %GND %NC %OUTY %VCC @MODEL; SAVECOUNT: 6; UPDATETIME: 19:30:29; UPDATEUSER: t5459927; TIME: 11:55:02; INSTANCENAME: INS2262788
IC24 = TC75S57FU: OriginalSymbolOrigin: (2540,0); PSPICETEMPLATE: X^@REFDES %INN %VSS %INP %OUT %VDD @MODEL; SAVECOUNT: 2; UPDATETIME: 11:03:38; UPDATEUSER: t5459927; TIME: 08:48:15; INSTANCENAME: INS2262824
IC27 = TC7WZ00FK_2: PART NUMBER: TC7W00FK; ORIGINALSYMBOLORIGIN: (2540,-2540); DESCRIPTION-A: NAND 2ch Logic; PSPICETEMPLATE: X^@REFDES %1A %1B %2Y %GND %2A %2B %1Y %VCC @MODEL; ・: 7 V; SPLIT_INST: TRUE; ORDER: $pOrder; SWAP_INFO: (S1+S2); SAVECOUNT: 9; UPDATETIME: 16:09:46; UPDATEUSER: sptcae09; TIME: 08:52:39; FUNCN: TC7WZ00FK_1; CaptureCellPackProp: TC7WZ00FK_2A
Q7 = 2SC5658J: ORIGINALSYMBOLORIGIN: (0,0); PSPICETEMPLATE: X^@REFDES %C %B %E @MODEL; SAVEAREA0: -6194,-158,18648,15662; VENDOR: ROHM; SAVECOUNT: 8; UPDATETIME: 15:12:10; UPDATEUSER: 19910145; TIME: 09:39:04; INSTANCENAME: INS2262598
Q8 = SSM3K15AFS: PSPICETEMPLATE: X^@REFDES %D %G %S @MODEL; ORIGINALSYMBOLORIGIN: (0,0); SAVECOUNT: 2; UPDATETIME: 08:48:15; UPDATEUSER: HP_Z8_KEYSHOT; INSTANCENAME: INS2262996
Q9 = SSM3K318R: PSPICETEMPLATE: X^@REFDES %D %G %S @MODEL; ORIGINALSYMBOLORIGIN: (0,0); SAVECOUNT: 2; UPDATETIME: 08:48:16; UPDATEUSER: HP_Z8_KEYSHOT; INSTANCENAME: INS2261964
Q10 = 2SC5658J: ORIGINALSYMBOLORIGIN: (0,0); PSPICETEMPLATE: X^@REFDES %C %B %E @MODEL; SAVEAREA0: -6194,-158,18648,15662; VENDOR: ROHM; SAVECOUNT: 8; UPDATETIME: 15:12:10; UPDATEUSER: 19910145; TIME: 09:39:04; INSTANCENAME: INS2262860
Q17 = SSM6K804R: PSPICETEMPLATE: X^@REFDES %1 %2 %3 %4 %5 %6 @MODEL; ORIGINALSYMBOLORIGIN: (0,0); SAVEAREA0: -7120,-295,29516,23636; SAVECOUNT: 14; UPDATETIME: 08:48:15; UPDATEUSER: HP_Z8_KEYSHOT; INSTANCENAME: INS2262956
R65-R71 R73 R74 R94 R95 R100 R101 R104 = R: as R187 on sheet 1
R72 = R: ORIGINALSYMBOLORIGIN: (0,0); PSPICETEMPLATE: R^@REFDES %1 %2 ?TOLERANCE¦R^@REFDES¦ @VALUE TC=@TC1,@TC2 ?TOLERANCE¦\n.model R^@REFDES RES R=1 DEV=@TOLERANCE% TC1=@TC1 TC2=@TC2¦; TC2: 0; VAL2: 100mW; SAVECOUNT: 2; UPDATETIME: 08:48:13; UPDATEUSER: HP_Z8_KEYSHOT; INSTANCENAME: INS2262084
R96 R102 = R: as R87 on sheet 2
TP39 = TP: ORIGINALSYMBOLORIGIN: (0,0); SAVEAREA0: -242,-92,12810,7836; SAVECOUNT: 2; UPDATETIME: 16:18:11; UPDATEUSER: fukuda-y; TIME: 16:12:21; INSTANCENAME: INS2262622
TP43 = TP: ORIGINALSYMBOLORIGIN: (0,0); SAVEAREA0: -242,-92,12810,7836; SAVECOUNT: 2; UPDATETIME: 16:18:11; UPDATEUSER: fukuda-y; TIME: 16:12:21; INSTANCENAME: INS2262916
U?#3 = WAKU_DEF100: OriginalSymbolOrigin: (10160,284480); SAVECOUNT: 4; UPDATETIME: 12:22:00; UPDATEUSER: t5459927; TIME: 14:30:25; SAVEAREA0: -63393,-16950,474261,314592; PLOTTIME: HH:MM; SHTSAVECOUNT: 28

## Sheet 4.SchDoc
size 420 x 297 mm
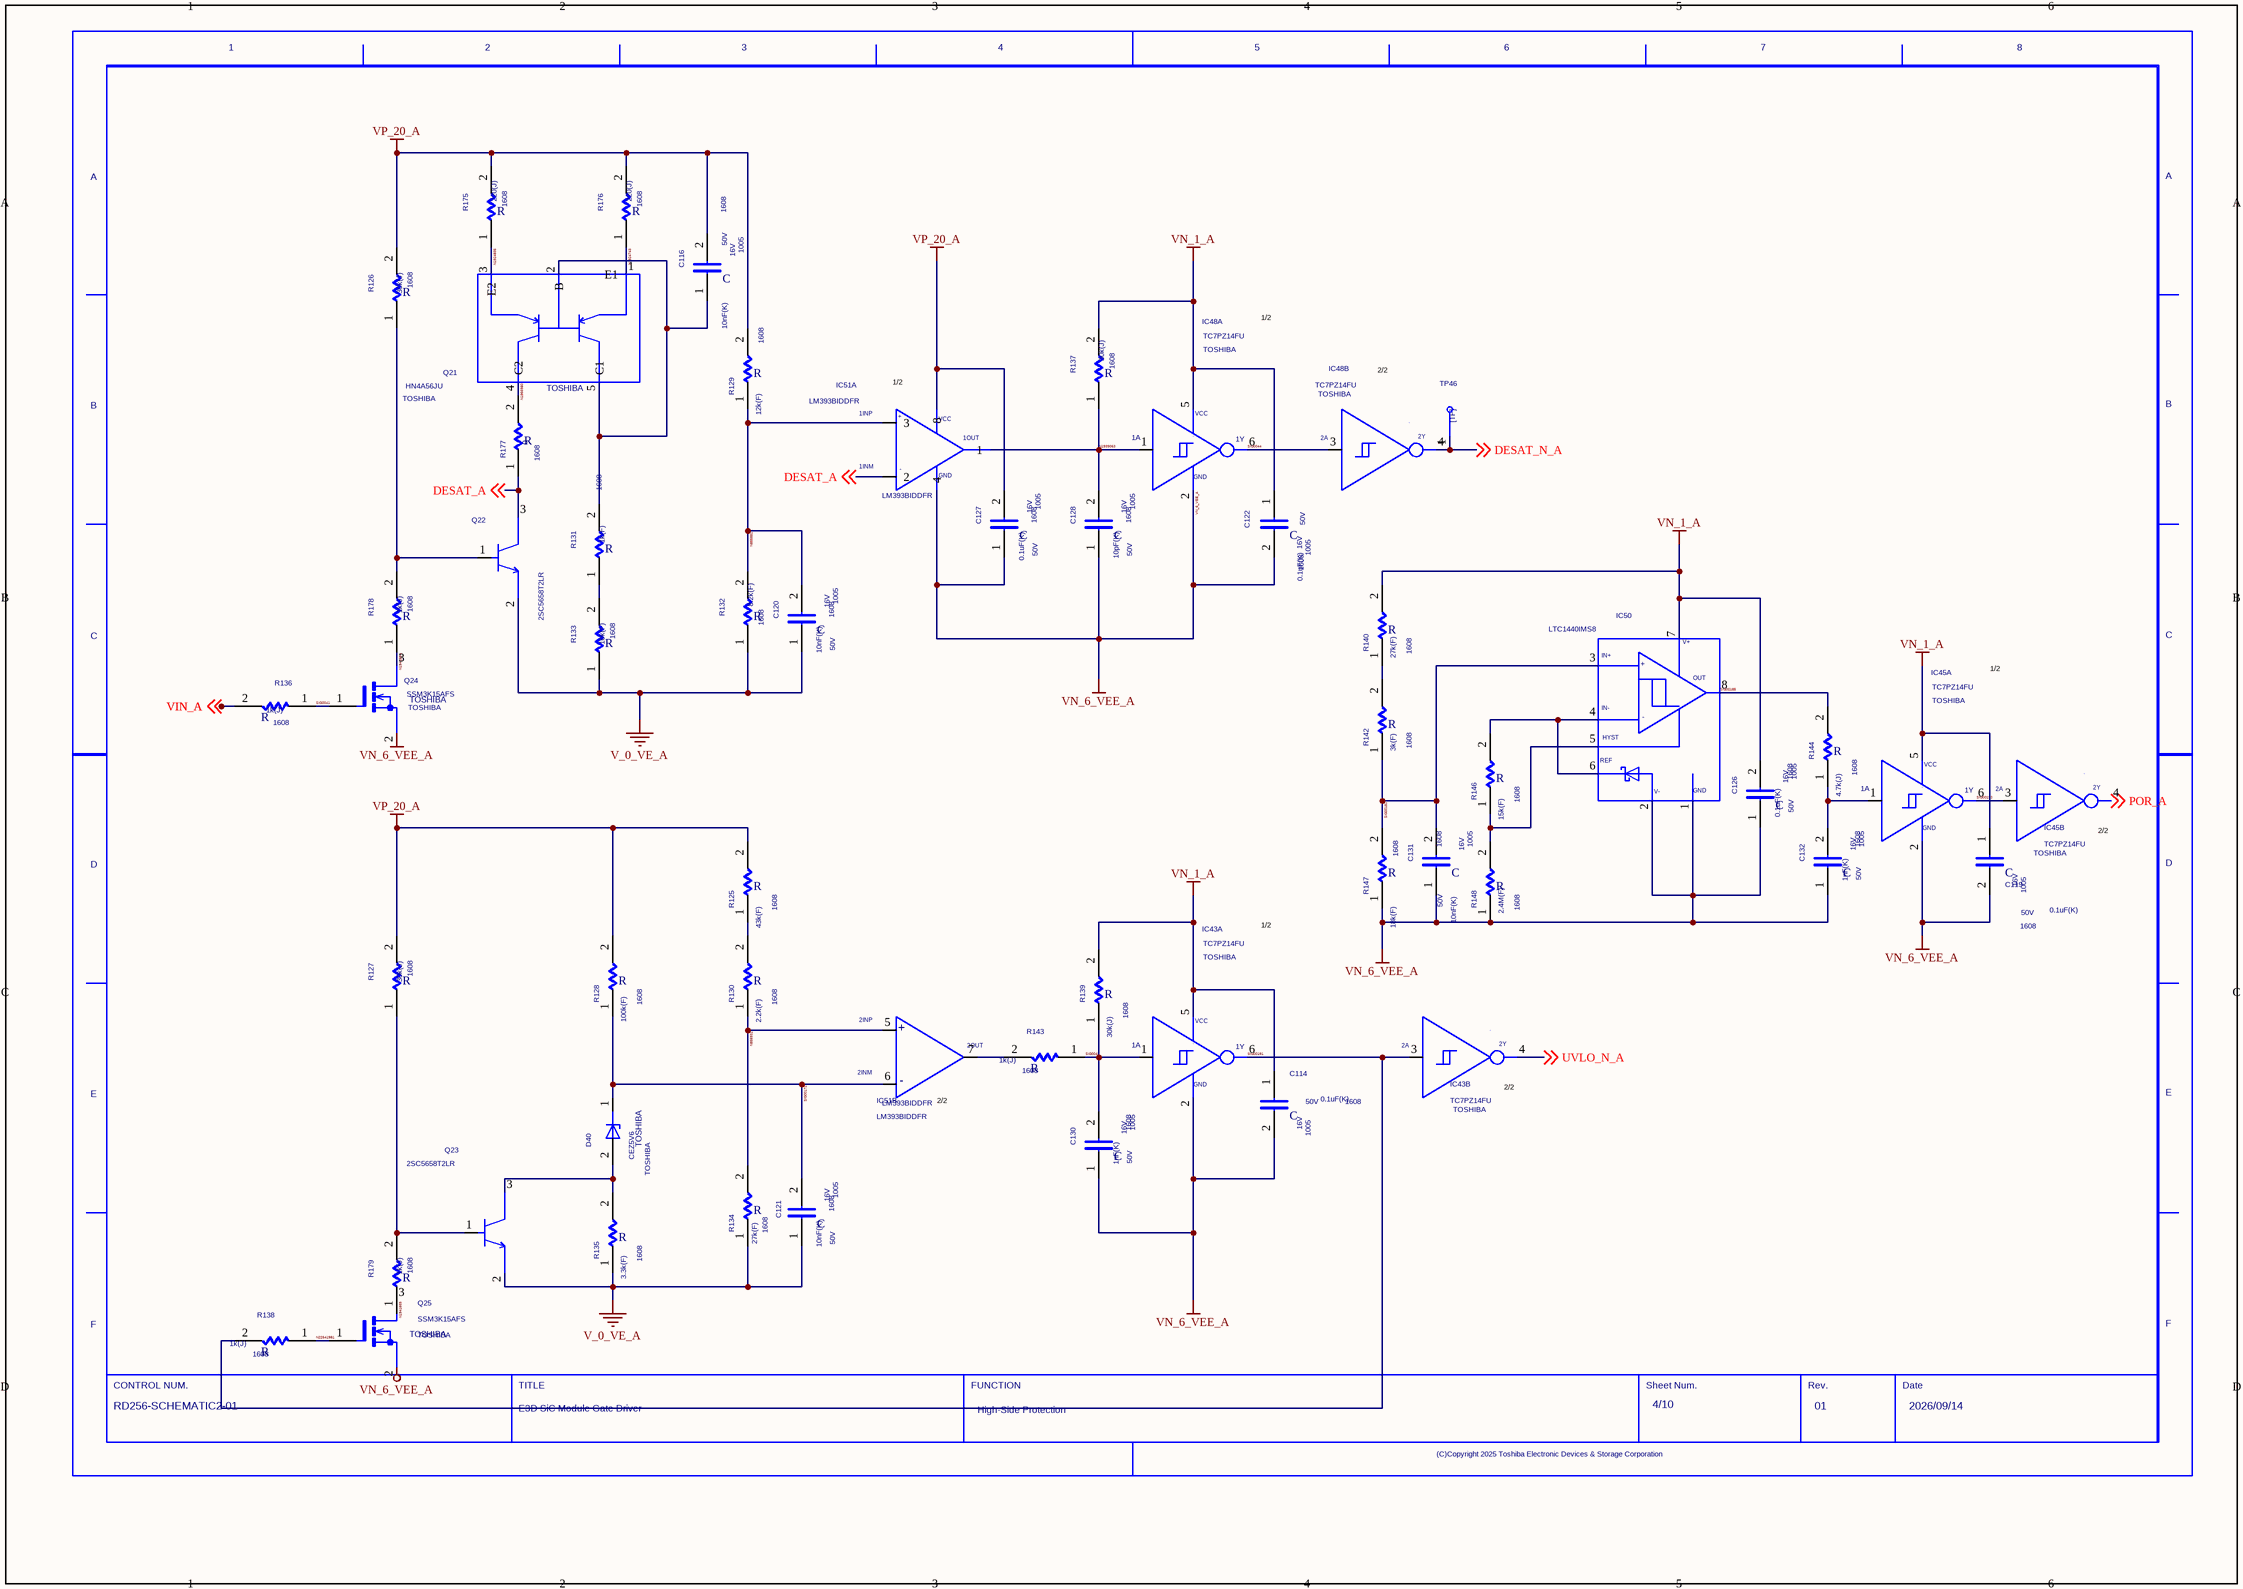
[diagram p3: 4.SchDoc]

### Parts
(Parts that share a designator on the sheet are numbered #1, #2 ... from top to bottom, then left to right.)
C114  VOLTAGE: 16V  CODE: 1005  VAL1: 0.1uF(K)  VAL2: 50V  SIZECODESMD: 1608  (hidden comment: C)
C116  VOLTAGE: 16V  CODE: 1005  VAL1: 10nF(K)  VAL2: 50V  SIZECODESMD: 1608  (hidden comment: C)
C119  VOLTAGE: 16V  CODE: 1005  VAL1: 0.1uF(K)  VAL2: 50V  SIZECODESMD: 1608  (hidden comment: C)
C120  VOLTAGE: 16V  CODE: 1005  VAL1: 10nF(K)  VAL2: 50V  SIZECODESMD: 1608  (hidden comment: C)
C121  VOLTAGE: 16V  CODE: 1005  VAL1: 10nF(K)  VAL2: 50V  SIZECODESMD: 1608  (hidden comment: C)
C122  VOLTAGE: 16V  CODE: 1005  VAL1: 0.1uF(K)  VAL2: 50V  SIZECODESMD: 1608  (hidden comment: C)
C126  VOLTAGE: 16V  CODE: 1005  VAL1: 0.1uF(K)  VAL2: 50V  SIZECODESMD: 1608  (hidden comment: C)
C127  VOLTAGE: 16V  CODE: 1005  VAL1: 0.1uF(K)  VAL2: 50V  SIZECODESMD: 1608  (hidden comment: C)
C128  VOLTAGE: 16V  CODE: 1005  VAL1: 10pF(K)  VAL2: 50V  SIZECODESMD: 1608  (hidden comment: C)
C130  VOLTAGE: 16V  CODE: 1005  VAL1: 1nF(K)  VAL2: 50V  SIZECODESMD: 1608  (hidden comment: C)
C131  VOLTAGE: 16V  CODE: 1005  VAL1: 10nF(K)  VAL2: 50V  SIZECODESMD: 1608  (hidden comment: C)
C132  VOLTAGE: 16V  CODE: 1005  VAL1: 1nF(K)  VAL2: 50V  SIZECODESMD: 1608  (hidden comment: C)
D40  VENDOR: TOSHIBA  (hidden comment: CEZ5V6)
IC43  VAL3: TC7PZ14FU  USERCOMPTEXT3: TOSHIBA  (hidden comment: TC7PZ17FU)  (parts A,B of 2)
IC45  VAL3: TC7PZ14FU  USERCOMPTEXT3: TOSHIBA  (hidden comment: TC7PZ17FU)  (parts A,B of 2)
IC48  VAL3: TC7PZ14FU  USERCOMPTEXT3: TOSHIBA  (hidden comment: TC7PZ17FU)  (parts A,B of 2)
IC50  VAL3: LTC1440IMS8  (hidden comment: LTC1440IS8)
IC51  VAL1: LM393BIDDFR  (hidden comment: LM393B_1)  (parts A,B of 2)
Q21  VENDOR: TOSHIBA  (hidden comment: HN4A56JU)
Q22  VAL3: 2SC5658T2LR  (hidden comment: 2SC5658J)
Q23  VAL3: 2SC5658T2LR  (hidden comment: 2SC5658J)
Q24  VENDOR: TOSHIBA  (hidden comment: SSM3K15AFS)
Q25  VENDOR: TOSHIBA  (hidden comment: SSM3K15AFS)
R125  VAL1: 43k(F)  SIZECODESMD: 1608  (hidden comment: R)
R126  VAL1: 30k(J)  SIZECODESMD: 1608  (hidden comment: R)
R127  VAL1: 30k(J)  SIZECODESMD: 1608  (hidden comment: R)
R128  VAL1: 100k(F)  SIZECODESMD: 1608  (hidden comment: R)
R129  VAL1: 12k(F)  SIZECODESMD: 1608  (hidden comment: R)
R130  VAL1: 2.2k(F)  SIZECODESMD: 1608  (hidden comment: R)
R131  VAL1: 1k(F)  SIZECODESMD: 1608  (hidden comment: R)
R132  VAL1: 8.2k(F)  SIZECODESMD: 1608  (hidden comment: R)
R133  VAL1: 10k(F)  SIZECODESMD: 1608  (hidden comment: R)
R134  VAL1: 27k(F)  SIZECODESMD: 1608  (hidden comment: R)
R135  VAL1: 3.3k(F)  SIZECODESMD: 1608  (hidden comment: R)
R136  VAL1: 1k(J)  SIZECODESMD: 1608  (hidden comment: R)
R137  VAL1: 30k(J)  SIZECODESMD: 1608  (hidden comment: R)
R138  VAL1: 1k(J)  SIZECODESMD: 1608  (hidden comment: R)
R139  VAL1: 30k(J)  SIZECODESMD: 1608  (hidden comment: R)
R140  VAL1: 27k(F)  SIZECODESMD: 1608  (hidden comment: R)
R142  VAL1: 3k(F)  SIZECODESMD: 1608  (hidden comment: R)
R143  VAL1: 1k(J)  SIZECODESMD: 1608  (hidden comment: R)
R144  VAL1: 4.7k(J)  SIZECODESMD: 1608  (hidden comment: R)
R146  VAL1: 15k(F)  SIZECODESMD: 1608  (hidden comment: R)
R147  VAL1: 18k(F)  SIZECODESMD: 1608  (hidden comment: R)
R148  VAL1: 2.4M(F)  SIZECODESMD: 1608  (hidden comment: R)
R175  VAL1: 220(J)  SIZECODESMD: 1608  (hidden comment: R)
R176  VAL1: 220(J)  SIZECODESMD: 1608  (hidden comment: R)
R177  VAL1: 0  SIZECODESMD: 1608  (hidden comment: R)
R178  VAL1: 1k(J)  SIZECODESMD: 1608  (hidden comment: R)
R179  VAL1: 1k(J)  SIZECODESMD: 1608  (hidden comment: R)
TP46  TP  (value not drawn)
U?#4  REVISION: 01  SHEETNUMBER: 4/10  FUNCTION: High-Side Protection  TITLE: E3D SiC Module Gate Driver  DRAWINGNUMBER: RD256-SCHEMATIC2-01  DATE: 2026/09/14  (hidden comment: WAKU_DEF100)

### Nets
V_0_VE_A: C120.1 C121.1 Q22.2(E) Q23.2(E) R132.1 R133.1 R134.1 R135.1
VN_1_A: C114.1 C119.1 C122.1 C126.2 IC43.5 IC45.5 IC48.5 IC50.7(V+) R137.2 R139.2 R140.2
VN_6_VEE_A: C114.2 C119.2 C122.2 C126.1 C127.1 C128.1 C130.1 C131.1 C132.1 IC43.2 IC45.2 IC48.2 IC50.1(GND) IC50.2(V-) IC51.4 Q24.2(S) Q25.2(S) R147.1 R148.1
VP_20_A: C116.2 C127.2 IC51.8 R125.2 R126.2 R127.2 R128.2 R129.2 R175.2 R176.2
DESAT_A: IC51.2 Q22.3(C) R177.1 ; off-sheet DESAT_A
DESAT_N_A: IC48.4 TP46.1 ; off-sheet DESAT_N_A
N855881: C120.2 IC51.3 R129.1 R132.2
N855931: IC51.5 R130.1 R134.2
N1924743: Q21.1(E1) R176.1
N1924835: Q21.3(E2) R175.1
N1939063: C128.2 IC48.1 IC51.1 R137.1
N1941594: Q24.3(D) R178.1
N1941665: Q25.3(D) R179.1
N1966980: Q21.4(C2) R177.2
N22641981: Q25.1(G) R138.1
POR_A: IC45.4 ; off-sheet POR_A
SIG0041: Q24.1(G) R136.1
SIG0043: C130.2 IC43.1 R139.1 R143.1
SIG0044: IC48.3 IC48.6
SIG00166: Q22.1(B) R126.1 R178.2
SIG00167: C116.1 Q21.2(B) Q21.5(C1) R131.2
SIG00168: R131.1 R133.2
SIG00170: Q23.1(B) R127.1 R179.2
SIG00171: D40.2(A) Q23.3(C) R135.2
SIG00172: C121.2 D40.1(C) IC51.6 R128.1
SIG00173: R125.1 R130.2
SIG00178: IC51.7 R143.2
SIG00180: R140.1 R142.2
SIG00181: C131.2 IC50.3(IN+) R142.1 R147.2
SIG00182: IC50.4(IN-) IC50.6(REF) R146.2
SIG00183: IC50.5(HYST) R146.1 R148.2
SIG00185: IC50.8(OUT) R144.2
SIG00186: C132.2 IC45.1 R144.1
SIG00191: IC43.3 IC43.6 R138.2
SIG00193: IC45.3 IC45.6
UVLO_N_A: IC43.4 ; off-sheet UVLO_N_A
VIN_A: R136.2 ; off-sheet VIN_A

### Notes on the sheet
- 1/2
- (near IC51) 1/2
- 2/2
- (near IC45) 2/2
- (near IC51) 2/2
- (near IC43) 2/2

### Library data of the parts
C114 C116 C119-C122 C126-C128 C130-C132 = C: as C24 on sheet 1
D40 = CEZ5V6: ORIGINALSYMBOLORIGIN: (0,0); PSPICETEMPLATE: X^@REFDES %C %A @MODEL; SAVEAREA0: -4630,-153,17114,13055; SAVECOUNT: 9; UPDATETIME: 08:16:22; UPDATEUSER: fukuda-y; TIME: 14:49:55; INSTANCENAME: INS2265024
IC43 IC45 IC48 = TC7PZ14FU_2: as IC44 on sheet 1
IC50 = LTC1440IS8: OriginalSymbolOrigin: (0,0); PSPICETEMPLATE: X^@REFDES %GND %V- %IN+ %IN- %HYST %REF %V+ %OUT @MODEL; SAVECOUNT: 4; UPDATETIME: 17:22:21; UPDATEUSER: t5459927; TIME: 08:48:16; INSTANCENAME: INS2264292
IC51 = LM393B_1: OriginalSymbolOrigin: (2540,0); SWAP_INFO: (S1+S2); VENDOR: TI; COMP: LM393B; PSPICETEMPLATE: X^@REFDES %INN %VSS %INP %OUT %VDD @MODEL; SPLIT_INST: TRUE; SAVECOUNT: 5; UPDATETIME: 19:15:42; UPDATEUSER: t5459927; TIME: 08:48:12; INSTANCENAME: INS2264892; CaptureCellPackProp: LM393B_1A
Q21 = HN4A56JU: OriginalSymbolOrigin: (0,0); PSPICETEMPLATE: X^@REFDES %B1 %E %B2 %C2 %C1 @MODEL; SAVECOUNT: 2; UPDATETIME: 08:48:13; UPDATEUSER: HP_Z8_KEYSHOT; INSTANCENAME: INS2265108
Q22 = 2SC5658J: ORIGINALSYMBOLORIGIN: (0,0); PSPICETEMPLATE: X^@REFDES %C %B %E @MODEL; SAVEAREA0: -6194,-158,18648,15662; VENDOR: ROHM; SAVECOUNT: 8; UPDATETIME: 15:12:10; UPDATEUSER: 19910145; TIME: 09:39:04; INSTANCENAME: INS2264212
Q23 = 2SC5658J: ORIGINALSYMBOLORIGIN: (0,0); PSPICETEMPLATE: X^@REFDES %C %B %E @MODEL; SAVEAREA0: -6194,-158,18648,15662; VENDOR: ROHM; SAVECOUNT: 8; UPDATETIME: 15:12:10; UPDATEUSER: 19910145; TIME: 09:39:04; INSTANCENAME: INS2264508
Q24 = SSM3K15AFS: PSPICETEMPLATE: X^@REFDES %D %G %S @MODEL; ORIGINALSYMBOLORIGIN: (0,0); SAVECOUNT: 2; UPDATETIME: 08:48:15; UPDATEUSER: HP_Z8_KEYSHOT; INSTANCENAME: INS2265300
Q25 = SSM3K15AFS: PSPICETEMPLATE: X^@REFDES %D %G %S @MODEL; ORIGINALSYMBOLORIGIN: (0,0); SAVECOUNT: 2; UPDATETIME: 08:48:15; UPDATEUSER: HP_Z8_KEYSHOT; INSTANCENAME: INS2264184
R125-R140 R142-R144 R146-R148 R175 R176 R178 R179 = R: as R187 on sheet 1
R177 = R: ORIGINALSYMBOLORIGIN: (0,0); PSPICETEMPLATE: R^@REFDES %1 %2 ?TOLERANCE¦R^@REFDES¦ @VALUE TC=@TC1,@TC2 ?TOLERANCE¦\n.model R^@REFDES RES R=1 DEV=@TOLERANCE% TC1=@TC1 TC2=@TC2¦; VAL2: 0.125; SAVECOUNT: 2; UPDATETIME: 08:48:13; UPDATEUSER: HP_Z8_KEYSHOT; INSTANCENAME: INS2264424
TP46 = TP: ORIGINALSYMBOLORIGIN: (0,0); SAVEAREA0: -242,-92,12810,7836; SAVECOUNT: 2; UPDATETIME: 16:18:11; UPDATEUSER: fukuda-y; TIME: 16:12:21; INSTANCENAME: INS2264820
U?#4 = WAKU_DEF100: OriginalSymbolOrigin: (10160,284480); SAVECOUNT: 4; UPDATETIME: 12:22:01; UPDATEUSER: t5459927; TIME: 14:30:25; SAVEAREA0: -63393,-16950,474261,314592; PLOTTIME: HH:MM; SHTSAVECOUNT: 30

## Sheet 5.SchDoc
size 420 x 297 mm
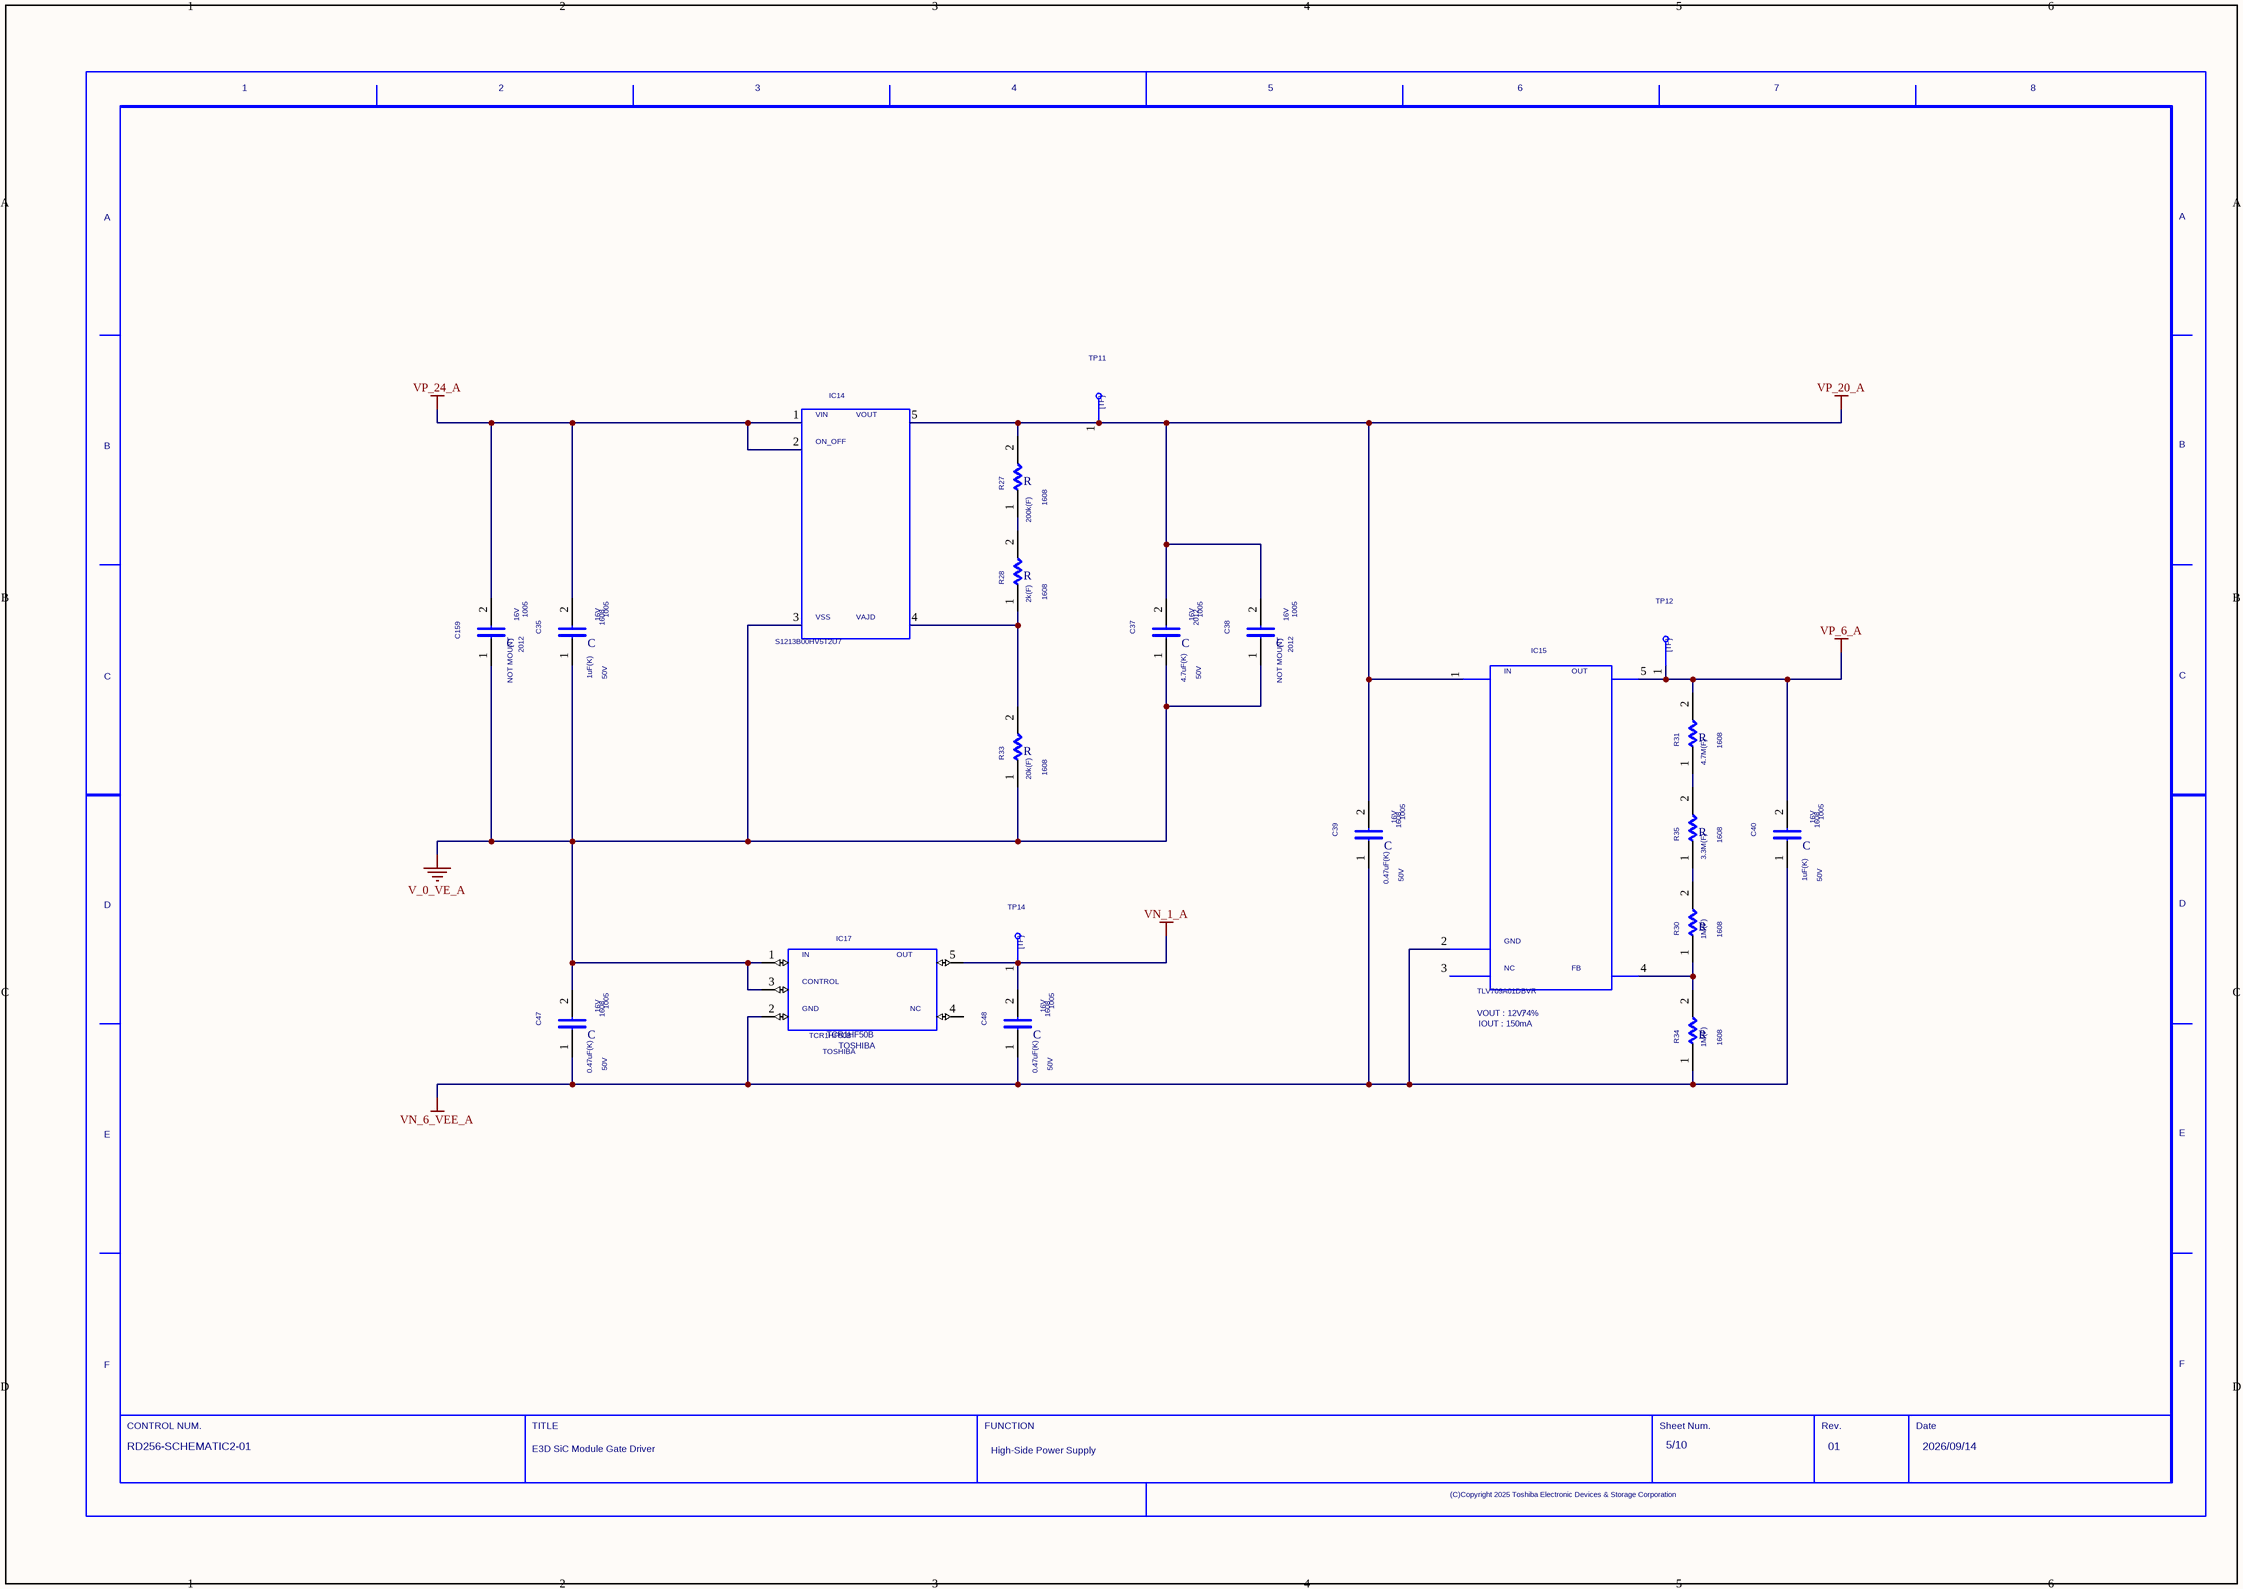
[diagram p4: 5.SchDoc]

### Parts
(Parts that share a designator on the sheet are numbered #1, #2 ... from top to bottom, then left to right.)
C35  VOLTAGE: 16V  CODE: 1005  VAL1: 1uF(K)  VAL2: 50V  SIZECODESMD: 1608  (hidden comment: C)
C37  VOLTAGE: 16V  CODE: 1005  VAL1: 4.7uF(K)  VAL2: 50V  SIZECODESMD: 2012  (hidden comment: C)
C38  VOLTAGE: 16V  CODE: 1005  SIZECODESMD: 2012  NOTMOUNT: NOT MOUNT  (hidden comment: C)
C39  VOLTAGE: 16V  CODE: 1005  VAL1: 0.47uF(K)  VAL2: 50V  SIZECODESMD: 1608  (hidden comment: C)
C40  VOLTAGE: 16V  CODE: 1005  VAL1: 1uF(K)  VAL2: 50V  SIZECODESMD: 1608  (hidden comment: C)
C47  VOLTAGE: 16V  CODE: 1005  VAL1: 0.47uF(K)  VAL2: 50V  SIZECODESMD: 1608  (hidden comment: C)
C48  VOLTAGE: 16V  CODE: 1005  VAL1: 0.47uF(K)  VAL2: 50V  SIZECODESMD: 1608  (hidden comment: C)
C159  VOLTAGE: 16V  CODE: 1005  SIZECODESMD: 2012  NOTMOUNT: NOT MOUNT  (hidden comment: C)
IC14  S1213B00HV5T2U7
IC15  CLASS: IOUT : 150mA  NC: VOUT : 12Vｱ4%  VAL3: TLV709A01DBVR  (hidden comment: TLV709)
IC17  TCR1HF50B  VENDOR: TOSHIBA
R27  VAL1: 200k(F)  SIZECODESMD: 1608  (hidden comment: R)
R28  VAL1: 2k(F)  SIZECODESMD: 1608  (hidden comment: R)
R30  VAL1: 1M(F)  SIZECODESMD: 1608  (hidden comment: R)
R31  VAL1: 4.7M(F)  SIZECODESMD: 1608  (hidden comment: R)
R33  VAL1: 20k(F)  SIZECODESMD: 1608  (hidden comment: R)
R34  VAL1: 1M(F)  SIZECODESMD: 1608  (hidden comment: R)
R35  VAL1: 3.3M(F)  SIZECODESMD: 1608  (hidden comment: R)
TP11  TP  (value not drawn)
TP12  TP  (value not drawn)
TP14  TP  (value not drawn)
U?#5  REVISION: 01  SHEETNUMBER: 5/10  FUNCTION: High-Side Power Supply  TITLE: E3D SiC Module Gate Driver  DRAWINGNUMBER: RD256-SCHEMATIC2-01  DATE: 2026/09/14  (hidden comment: WAKU_DEF100)

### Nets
V_0_VE_A: C35.1 C37.1 C38.1 C47.2 C159.1 IC14.3 IC17.1 IC17.3 R33.1
VN_1_A: C48.2 IC17.5 TP14.1
VN_6_VEE_A: C39.1 C40.1 C47.1 C48.1 IC15.2 IC17.2 R34.1
VP_6_A: C40.2 IC15.5 R31.2 TP12.1
VP_20_A: C37.2 C38.2 C39.2 IC14.5 IC15.1 R27.2 TP11.1
VP_24_A: C35.2 C159.2 IC14.1 IC14.2
SIG00045: R27.1 R28.2
SIG00046: IC14.4 R28.1 R33.2
SIG00047: IC15.4 R30.1 R34.2
SIG00048: R30.2 R35.1
SIG00049: R31.1 R35.2

Not connected (* = marked no-connect by the designer): IC15 3; IC17 4

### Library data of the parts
C35 C37-C40 C47 C48 C159 = C: as C91 on sheet 2
IC14 = S1213B00HV5T2U7: OriginalSymbolOrigin: (0,0); PSPICETEMPLATE: X^@REFDES %ADJUST %OUTPUT %INPUT @MODEL; SAVECOUNT: 7; UPDATETIME: 09:48:38; UPDATEUSER: t5459927; TIME: 08:48:13; INSTANCENAME: INS2266489
IC15 = TLV709: OriginalSymbolOrigin: (0,0); PSPICETEMPLATE: X^@REFDES %IN %GND %NC %FB %OUT @MODEL; SAVECOUNT: 5; UPDATETIME: 10:01:49; UPDATEUSER: t5459927; TIME: 08:48:16; INSTANCENAME: INS2266385
IC17 = TCR1HF50B: OriginalSymbolOrigin: (-2540,0); PSPICETEMPLATE: X^@REFDES %IN %GND %CONTROL %NC %OUT @MODEL; SAVECOUNT: 4; UPDATETIME: 10:27:35; UPDATEUSER: t5459927; TIME: 11:54:59; INSTANCENAME: INS2266087
R27 R28 R30 R31 R33-R35 = R: as R89 on sheet 2
TP11 = TP: ORIGINALSYMBOLORIGIN: (0,0); SAVEAREA0: -242,-92,12810,7836; SAVECOUNT: 2; UPDATETIME: 16:18:11; UPDATEUSER: fukuda-y; TIME: 16:12:21; INSTANCENAME: INS2266317
TP12 = TP: ORIGINALSYMBOLORIGIN: (0,0); SAVEAREA0: -242,-92,12810,7836; SAVECOUNT: 2; UPDATETIME: 16:18:11; UPDATEUSER: fukuda-y; TIME: 16:12:21; INSTANCENAME: INS2266305
TP14 = TP: ORIGINALSYMBOLORIGIN: (0,0); SAVEAREA0: -242,-92,12810,7836; SAVECOUNT: 2; UPDATETIME: 16:18:11; UPDATEUSER: fukuda-y; TIME: 16:12:21; INSTANCENAME: INS2266293
U?#5 = WAKU_DEF100: OriginalSymbolOrigin: (10160,284480); SAVECOUNT: 4; UPDATETIME: 11:30:53; UPDATEUSER: t5459927; TIME: 14:30:25; SAVEAREA0: -63393,-16950,474261,314592; PLOTTIME: HH:MM; SHTSAVECOUNT: 21

## Sheet 6.SchDoc
size 420 x 297 mm
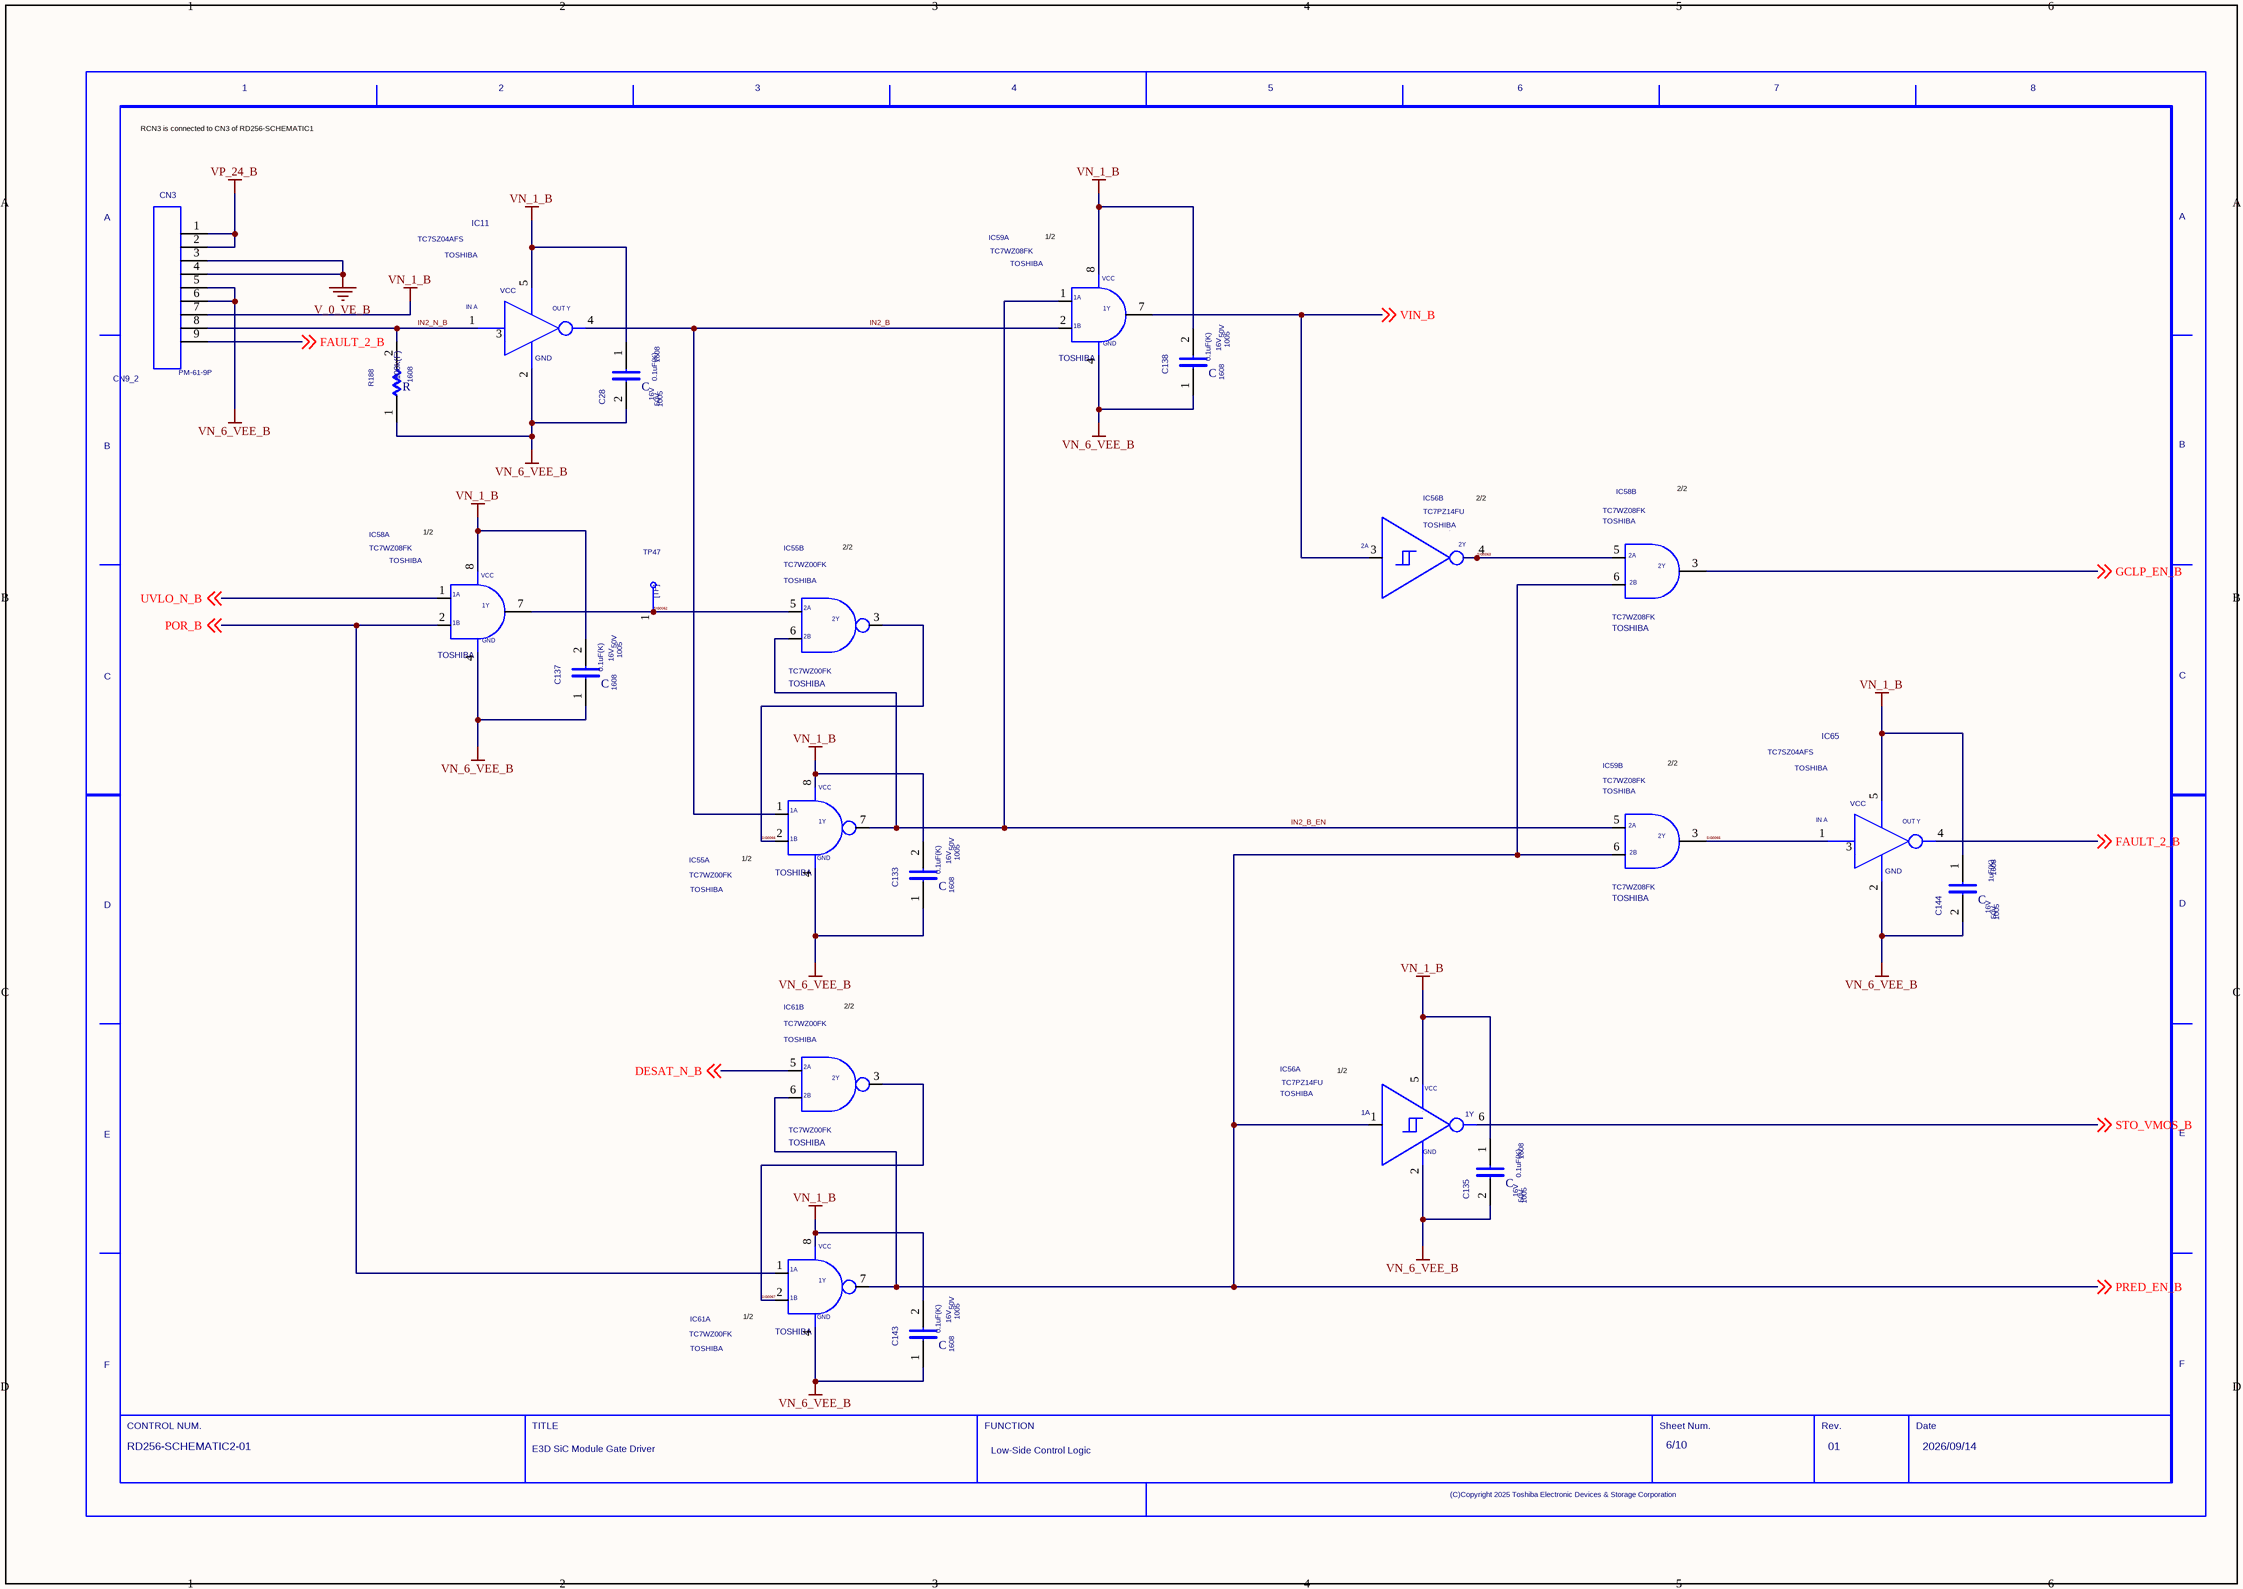
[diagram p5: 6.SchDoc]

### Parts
(Parts that share a designator on the sheet are numbered #1, #2 ... from top to bottom, then left to right.)
C28  VOLTAGE: 16V  CODE: 1005  VAL1: 0.1uF(K)  VAL2: 50V  SIZECODESMD: 1608  (hidden comment: C)
C133  VOLTAGE: 16V  CODE: 1005  VAL1: 0.1uF(K)  VAL2: 50V  SIZECODESMD: 1608  (hidden comment: C)
C135  VOLTAGE: 16V  CODE: 1005  VAL1: 0.1uF(K)  VAL2: 50V  SIZECODESMD: 1608  (hidden comment: C)
C137  VOLTAGE: 16V  CODE: 1005  VAL1: 0.1uF(K)  VAL2: 50V  SIZECODESMD: 1608  (hidden comment: C)
C138  VOLTAGE: 16V  CODE: 1005  VAL1: 0.1uF(K)  VAL2: 50V  SIZECODESMD: 1608  (hidden comment: C)
C143  VOLTAGE: 16V  CODE: 1005  VAL1: 0.1uF(K)  VAL2: 50V  SIZECODESMD: 1608  (hidden comment: C)
C144  VOLTAGE: 16V  CODE: 1005  VAL1: 1uF(K)  VAL2: 50V  SIZECODESMD: 1608  (hidden comment: C)
CN3  CN9_2  VAL3: PM-61-9P
IC11  USERCOMPTEXT3: TOSHIBA  (hidden comment: TC7SZ04AFS)
IC55  VENDOR: TOSHIBA  (hidden comment: TC7WZ00FK)  (parts A,B of 2)
IC56  VAL3: TC7PZ14FU  USERCOMPTEXT3: TOSHIBA  (hidden comment: TC7PZ17FU)  (parts A,B of 2)
IC58  VENDOR: TOSHIBA  (hidden comment: TC7WZ08FK)  (parts A,B of 2)
IC59  VENDOR: TOSHIBA  (hidden comment: TC7WZ08FK)  (parts A,B of 2)
IC61  VENDOR: TOSHIBA  (hidden comment: TC7WZ00FK)  (parts A,B of 2)
IC65  USERCOMPTEXT3: TOSHIBA  (hidden comment: TC7SZ04AFS)
R188  VAL1: 100k(F)  SIZECODESMD: 1608  (hidden comment: R)
TP47  TP  (value not drawn)
U?#6  REVISION: 01  SHEETNUMBER: 6/10  FUNCTION: Low-Side Control Logic  TITLE: E3D SiC Module Gate Driver  DRAWINGNUMBER: RD256-SCHEMATIC2-01  DATE: 2026/09/14  (hidden comment: WAKU_DEF100)

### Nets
V_0_VE_B: CN3.3 CN3.4
VN_1_B: C28.1 C133.2 C135.1 C137.2 C138.2 C143.2 C144.1 CN3.7 IC11.5 IC55.8 IC56.5 IC58.8 IC59.8 IC61.8 IC65.5
VN_6_VEE_B: C28.2 C133.1 C135.2 C137.1 C138.1 C143.1 C144.2 CN3.5 CN3.6 IC11.2 IC55.4 IC56.2 IC58.4 IC59.4 IC61.4 IC65.2 R188.1
VP_24_B: CN3.1 CN3.2
DESAT_N_B: IC61.5(2A) ; off-sheet DESAT_N_B
FAULT_2_B: CN3.9 IC65.4 ; off-sheet FAULT_2_B
GCLP_EN_B: IC58.3 ; off-sheet GCLP_EN_B
IN2_B: IC11.4 IC55.1 IC59.2
IN2_B_EN: IC55.6(2B) IC55.7 IC59.1 IC59.5
IN2_N_B: CN3.8 IC11.1 R188.2
POR_B: IC58.2 IC61.1 ; off-sheet POR_B
PRED_EN_B: IC56.1 IC58.6 IC59.6 IC61.6(2B) IC61.7 ; off-sheet PRED_EN_B
SIG0062: IC55.5(2A) IC58.7 TP47.1
SIG0063: IC56.4 IC58.5
SIG0065: IC59.3 IC65.1
SIG0066: IC55.2 IC55.3(2Y)
SIG0067: IC61.2 IC61.3(2Y)
STO_VMOS_B: IC56.6 ; off-sheet STO_VMOS_B
UVLO_N_B: IC58.1 ; off-sheet UVLO_N_B
VIN_B: IC56.3 IC59.7 ; off-sheet VIN_B

Not connected (* = marked no-connect by the designer): IC11 3; IC65 3

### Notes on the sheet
- RCN3 is connected to CN3 of RD256-SCHEMATIC1
- (near IC59) 1/2
- (near IC58) 1/2
- 2/2
- (near IC55) 1/2
- (near IC56) 1/2
- (near IC61) 1/2

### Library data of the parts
C28 C133 C135 C137 C138 C143 C144 = C: as C24 on sheet 1
CN3 = CN9_1: as CN2 on sheet 1
IC11 IC65 = TC7SZ04AFS: as IC7 on sheet 1
IC55 IC61 = TC7WZ00FK_2: as IC42 on sheet 1
IC56 = TC7PZ14FU_2: as IC44 on sheet 1
IC58 IC59 = TC7WZ08FK_1: as IC46 on sheet 1
R188 = R: as R187 on sheet 1
TP47 = TP: as TP45 on sheet 1
U?#6 = WAKU_DEF100: OriginalSymbolOrigin: (10160,284480); SAVECOUNT: 4; UPDATETIME: 12:22:00; UPDATEUSER: t5459927; TIME: 14:30:25; SAVEAREA0: -63393,-16950,474261,314592; PLOTTIME: HH:MM; SHTSAVECOUNT: 33

## Sheet 7.SchDoc
size 420 x 297 mm
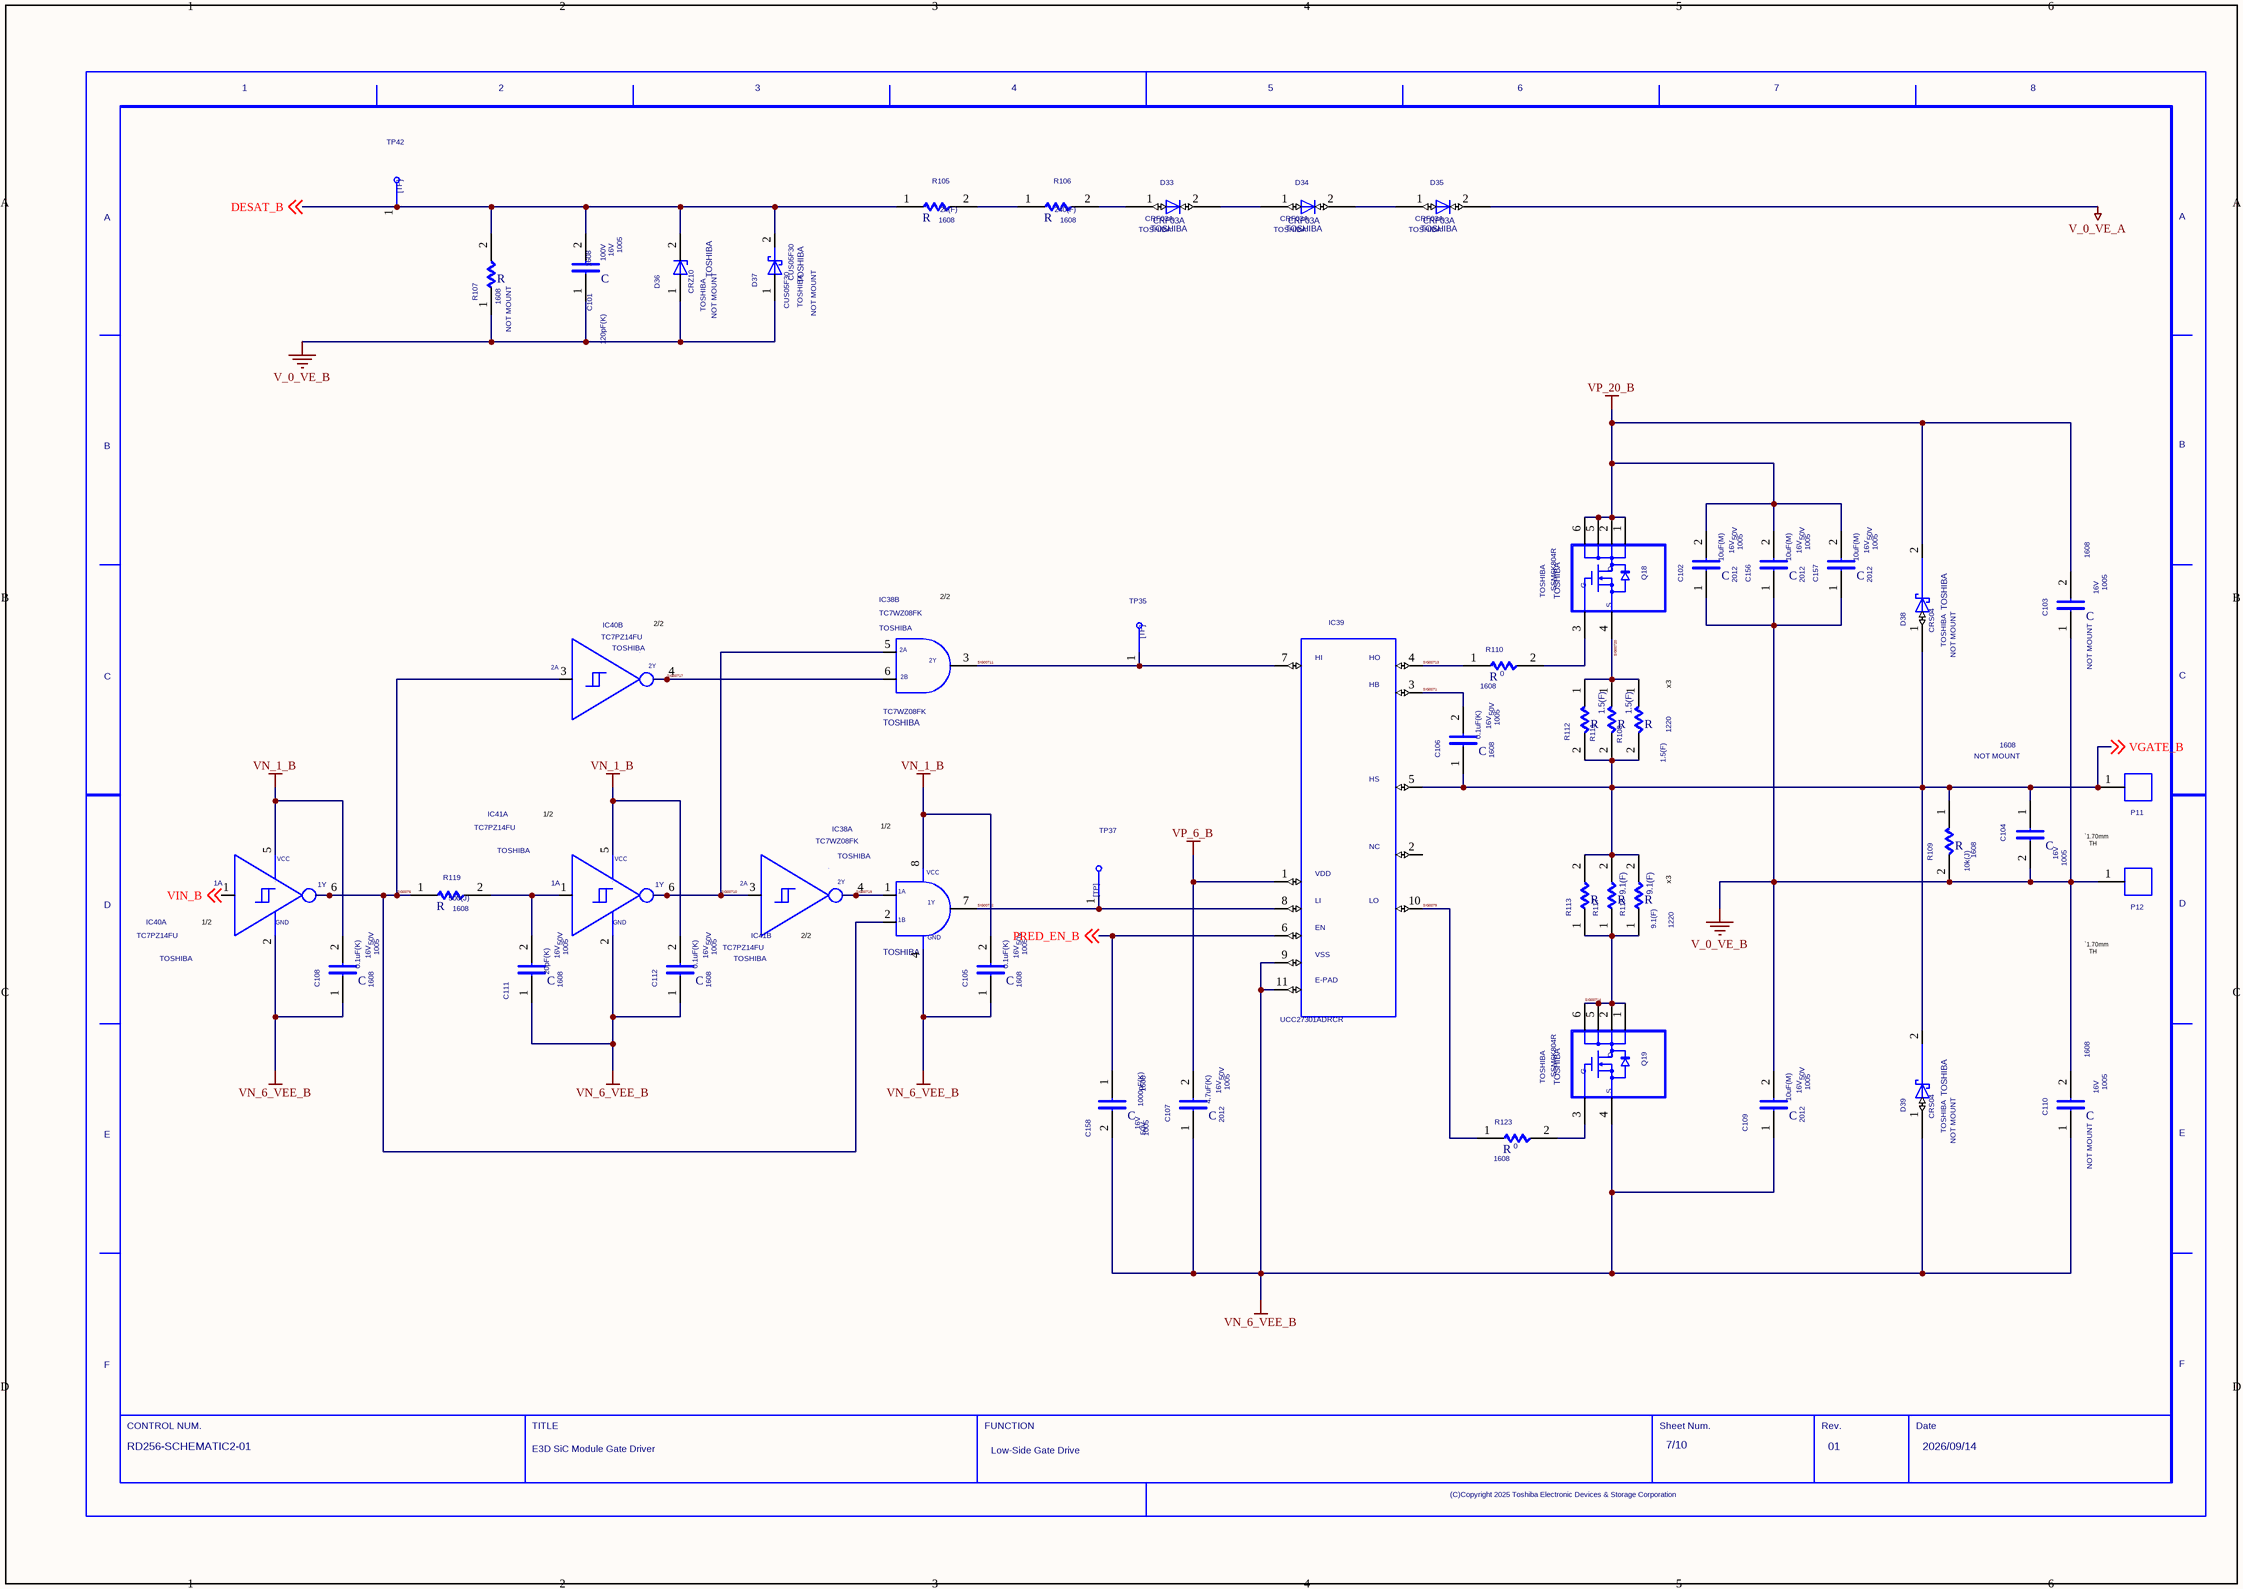
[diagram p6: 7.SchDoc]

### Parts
(Parts that share a designator on the sheet are numbered #1, #2 ... from top to bottom, then left to right.)
C101  VOLTAGE: 16V  CODE: 1005  VAL1: 120pF(K)  VAL2: 100V  SIZECODESMD: 1608  (hidden comment: C)
C102  VOLTAGE: 16V  CODE: 1005  VAL1: 10uF(M)  VAL2: 50V  SIZECODESMD: 2012  (hidden comment: C)
C103  VOLTAGE: 16V  CODE: 1005  SIZECODESMD: 1608  NOTMOUNT: NOT MOUNT  (hidden comment: C)
C104  VOLTAGE: 16V  CODE: 1005  SIZECODESMD: 1608  NOTMOUNT: NOT MOUNT  (hidden comment: C)
C105  VOLTAGE: 16V  CODE: 1005  VAL1: 0.1uF(K)  VAL2: 50V  SIZECODESMD: 1608  (hidden comment: C)
C106  VOLTAGE: 16V  CODE: 1005  VAL1: 0.1uF(K)  VAL2: 50V  SIZECODESMD: 1608  (hidden comment: C)
C107  VOLTAGE: 16V  CODE: 1005  VAL1: 4.7uF(K)  VAL2: 50V  SIZECODESMD: 2012  (hidden comment: C)
C108  VOLTAGE: 16V  CODE: 1005  VAL1: 0.1uF(K)  VAL2: 50V  SIZECODESMD: 1608  (hidden comment: C)
C109  VOLTAGE: 16V  CODE: 1005  VAL1: 10uF(M)  VAL2: 50V  SIZECODESMD: 2012  (hidden comment: C)
C110  VOLTAGE: 16V  CODE: 1005  SIZECODESMD: 1608  NOTMOUNT: NOT MOUNT  (hidden comment: C)
C111  VOLTAGE: 16V  CODE: 1005  VAL1: 20pF(K)  VAL2: 50V  SIZECODESMD: 1608  (hidden comment: C)
C112  VOLTAGE: 16V  CODE: 1005  VAL1: 0.1uF(K)  VAL2: 50V  SIZECODESMD: 1608  (hidden comment: C)
C156  VOLTAGE: 16V  CODE: 1005  VAL1: 10uF(M)  VAL2: 50V  SIZECODESMD: 2012  (hidden comment: C)
C157  VOLTAGE: 16V  CODE: 1005  VAL1: 10uF(M)  VAL2: 50V  SIZECODESMD: 2012  (hidden comment: C)
C158  VOLTAGE: 16V  CODE: 1005  VAL1: 1000pF(K)  VAL2: 50V  SIZECODESMD: 1608  (hidden comment: C)
D33  VENDOR: TOSHIBA  (hidden comment: CRF03A)
D34  VENDOR: TOSHIBA  (hidden comment: CRF03A)
D35  VENDOR: TOSHIBA  (hidden comment: CRF03A)
D36  VENDOR: TOSHIBA  NOTMOUNT: NOT MOUNT  (hidden comment: CRZ10)
D37  VENDOR: TOSHIBA  NOTMOUNT: NOT MOUNT  (hidden comment: CUS05F30)
D38  VENDOR: TOSHIBA  NOTMOUNT: NOT MOUNT  (hidden comment: CRS04)
D39  VENDOR: TOSHIBA  NOTMOUNT: NOT MOUNT  (hidden comment: CRS04)
IC38  VENDOR: TOSHIBA  (hidden comment: TC7WZ08FK)  (parts A,B of 2)
IC39  VAL3: UCC27301ADRCR  (hidden comment: UCC27301A)
IC40  VAL3: TC7PZ14FU  USERCOMPTEXT3: TOSHIBA  (hidden comment: TC7PZ17FU)  (parts A,B of 2)
IC41  VAL3: TC7PZ14FU  USERCOMPTEXT3: TOSHIBA  (hidden comment: TC7PZ17FU)  (parts A,B of 2)
P11  TH  (value not drawn)
P12  TH  (value not drawn)
Q18  VENDOR: TOSHIBA  (hidden comment: SSM6K804R)
Q19  VENDOR: TOSHIBA  (hidden comment: SSM6K804R)
R105  VAL1: 2k(F)  SIZECODESMD: 1608  (hidden comment: R)
R106  VAL1: 240(F)  SIZECODESMD: 1608  (hidden comment: R)
R107  SIZECODESMD: 1608  NOTMOUNT: NOT MOUNT  (hidden comment: R)
R108  VAL1: 1.5(F)  (hidden comment: R)
R109  VAL1: 10k(J)  SIZECODESMD: 1608  (hidden comment: R)
R110  VAL1: 0  SIZECODESMD: 1608  (hidden comment: R)
R111  VAL1: 1.5(F)  (hidden comment: R)
R112  VAL1: 1.5(F)  SIZECODESMD: 1220  (hidden comment: R)
R113  VAL1: 9.1(F)  SIZECODESMD: 1220  (hidden comment: R)
R117  VAL1: 9.1(F)  (hidden comment: R)
R118  VAL1: 9.1(F)  (hidden comment: R)
R119  VAL1: 500(J)  SIZECODESMD: 1608  (hidden comment: R)
R123  VAL1: 0  SIZECODESMD: 1608  (hidden comment: R)
TP35  TP  (value not drawn)
TP37  TP  (value not drawn)
TP42  TP  (value not drawn)
U?#7  REVISION: 01  SHEETNUMBER: 7/10  FUNCTION: Low-Side Gate Drive  TITLE: E3D SiC Module Gate Driver  DRAWINGNUMBER: RD256-SCHEMATIC2-01  DATE: 2026/09/14  (hidden comment: WAKU_DEF100)

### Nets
V_0_VE_A: D35.2(C)
V_0_VE_B: C101.1 C102.1 C103.1 C104.2 C109.2 C110.2 C156.1 C157.1 D36.1(A) D37.1(A) P12.1 R107.1 R109.2
VN_1_B: C105.2 C108.2 C112.2 IC38.8 IC40.5 IC41.5
VN_6_VEE_B: C105.1 C107.1 C108.1 C109.1 C110.1 C111.1 C112.1 C158.2 D39.1(A) IC38.4 IC39.9 IC39.11 IC40.2 IC41.2 Q19.4
VP_6_B: C107.2 IC39.1
VP_20_B: C102.2 C103.2 C156.2 C157.2 D38.2(C) Q18.1 Q18.2 Q18.5 Q18.6
DESAT_B: C101.2 D36.2(C) D37.2(C) R105.1 R107.2 TP42.1 ; off-sheet DESAT_B
PRED_EN_B: C158.1 IC39.6 ; off-sheet PRED_EN_B
SIG0071: C106.2 IC39.3
SIG0072: D33.2(C) D34.1(A)
SIG0073: D33.1(A) R106.2
SIG0075: Q18.3 R110.2
SIG0076: IC38.2 IC40.3 IC40.6 R119.1
SIG0077: D34.2(C) D35.1(A)
SIG0078: R105.2 R106.1
SIG0079: IC39.10 R123.1
SIG00710: IC38.5 IC41.3 IC41.6
SIG00711: IC38.3 IC39.7 TP35.1
SIG00712: IC38.7 IC39.8 TP37.1
SIG00713: IC39.4 R110.1
SIG00714: Q19.1 Q19.2 Q19.5 Q19.6 R113.1 R117.1 R118.1
SIG00716: C111.2 IC41.1 R119.2
SIG00717: IC38.6 IC40.4
SIG00718: Q19.3 R123.2
SIG00719: IC38.1 IC41.4
SIG00720: Q18.4 R108.1 R111.1 R112.1
VGATE_B: C104.1 C106.1 D38.1(A) D39.2(C) IC39.5 P11.1 R108.2 R109.1 R111.2 R112.2 R113.2 R117.2 R118.2 ; off-sheet VGATE_B
VIN_B: IC40.1 ; off-sheet VIN_B

Not connected (* = marked no-connect by the designer): IC39 2

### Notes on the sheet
- (near IC38) 2/2
- (near IC40) 2/2
- (near R108) x3
- (near IC41) 1/2
- (near IC38) 1/2
- `1.70mm
  TH
- (near IC40) 1/2
- (near IC41) 2/2
- (near R118) x3

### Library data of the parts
C101 C102 C105-C109 C111 C112 C156-C158 = C: as C24 on sheet 1
C103 C104 C110 = C: as C91 on sheet 2
D33-D35 = CRF03A: as D26 on sheet 2
D36 = CRZ10: as D29 on sheet 2
D37 = CUS05F30: as D30 on sheet 2
D38 D39 = CRS04: as D31 on sheet 2
IC38 = TC7WZ08FK_1: as IC34 on sheet 2
IC39 = UCC27301A: as IC35 on sheet 2
IC40 IC41 = TC7PZ14FU_2: OriginalSymbolOrigin: (5080,15240); SWAP_INFO: (S1+S2); PSPICETEMPLATE: X^@REFDES %1A %GND %2A %2Y %VCC %1Y @MODEL; SPLIT_INST: TRUE; SAVECOUNT: 4; UPDATETIME: 19:09:34; UPDATEUSER: t5459927; TIME: 11:55:01; INSTANCENAME: INS2255542; FUNCN: TC7PZ14FU_1; CaptureCellPackProp: TC7PZ14FU_2A
P11 = TH: as P4 on sheet 2
P12 = TH: as P5 on sheet 2
Q18 Q19 = SSM6K804R: as Q15 on sheet 2
R105 R106 R119 = R: as R187 on sheet 1
R107 = R: as R87 on sheet 2
R108 R111 R117 R118 = R: as R91 on sheet 2
R109 = R: as R89 on sheet 2
R110 R123 = R: as R90 on sheet 2
R112 R113 = R: as R88 on sheet 2
TP35 = TP: as TP30 on sheet 2
TP37 = TP: as TP32 on sheet 2
TP42 = TP: as TP41 on sheet 2
U?#7 = WAKU_DEF100: as U?#4 on sheet 4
